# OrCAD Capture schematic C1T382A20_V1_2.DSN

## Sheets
1 002_POWER TREE: title: TELINK; rev: V1.2; note: C1T382A20
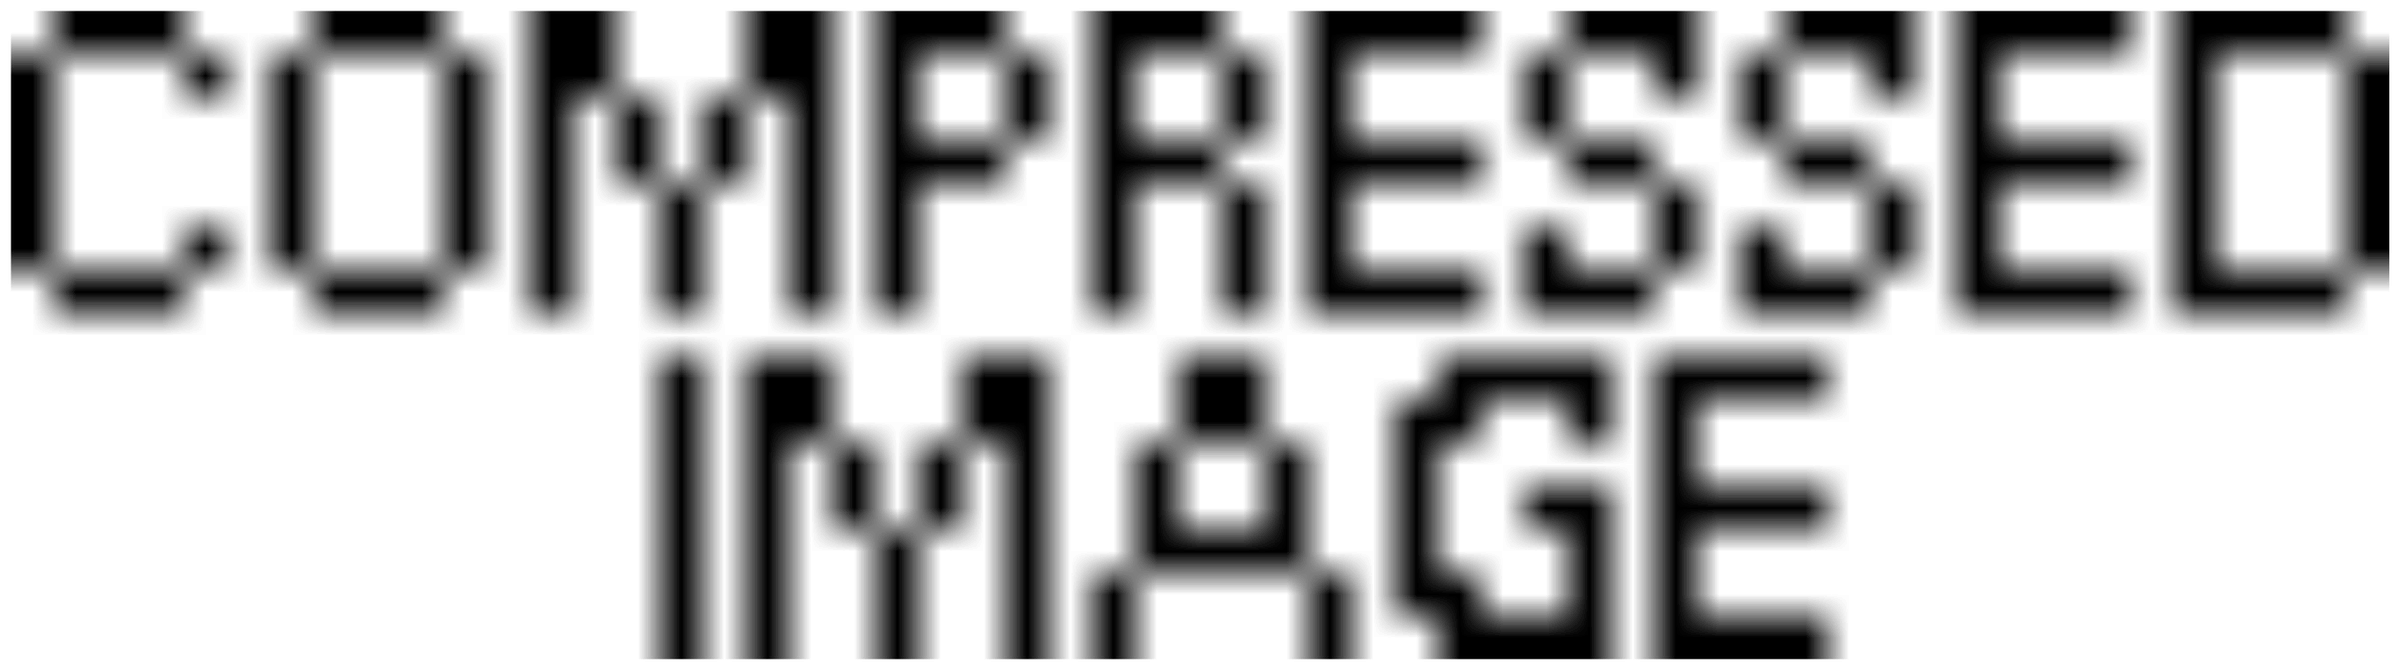
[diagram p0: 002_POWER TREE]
2 000_Log
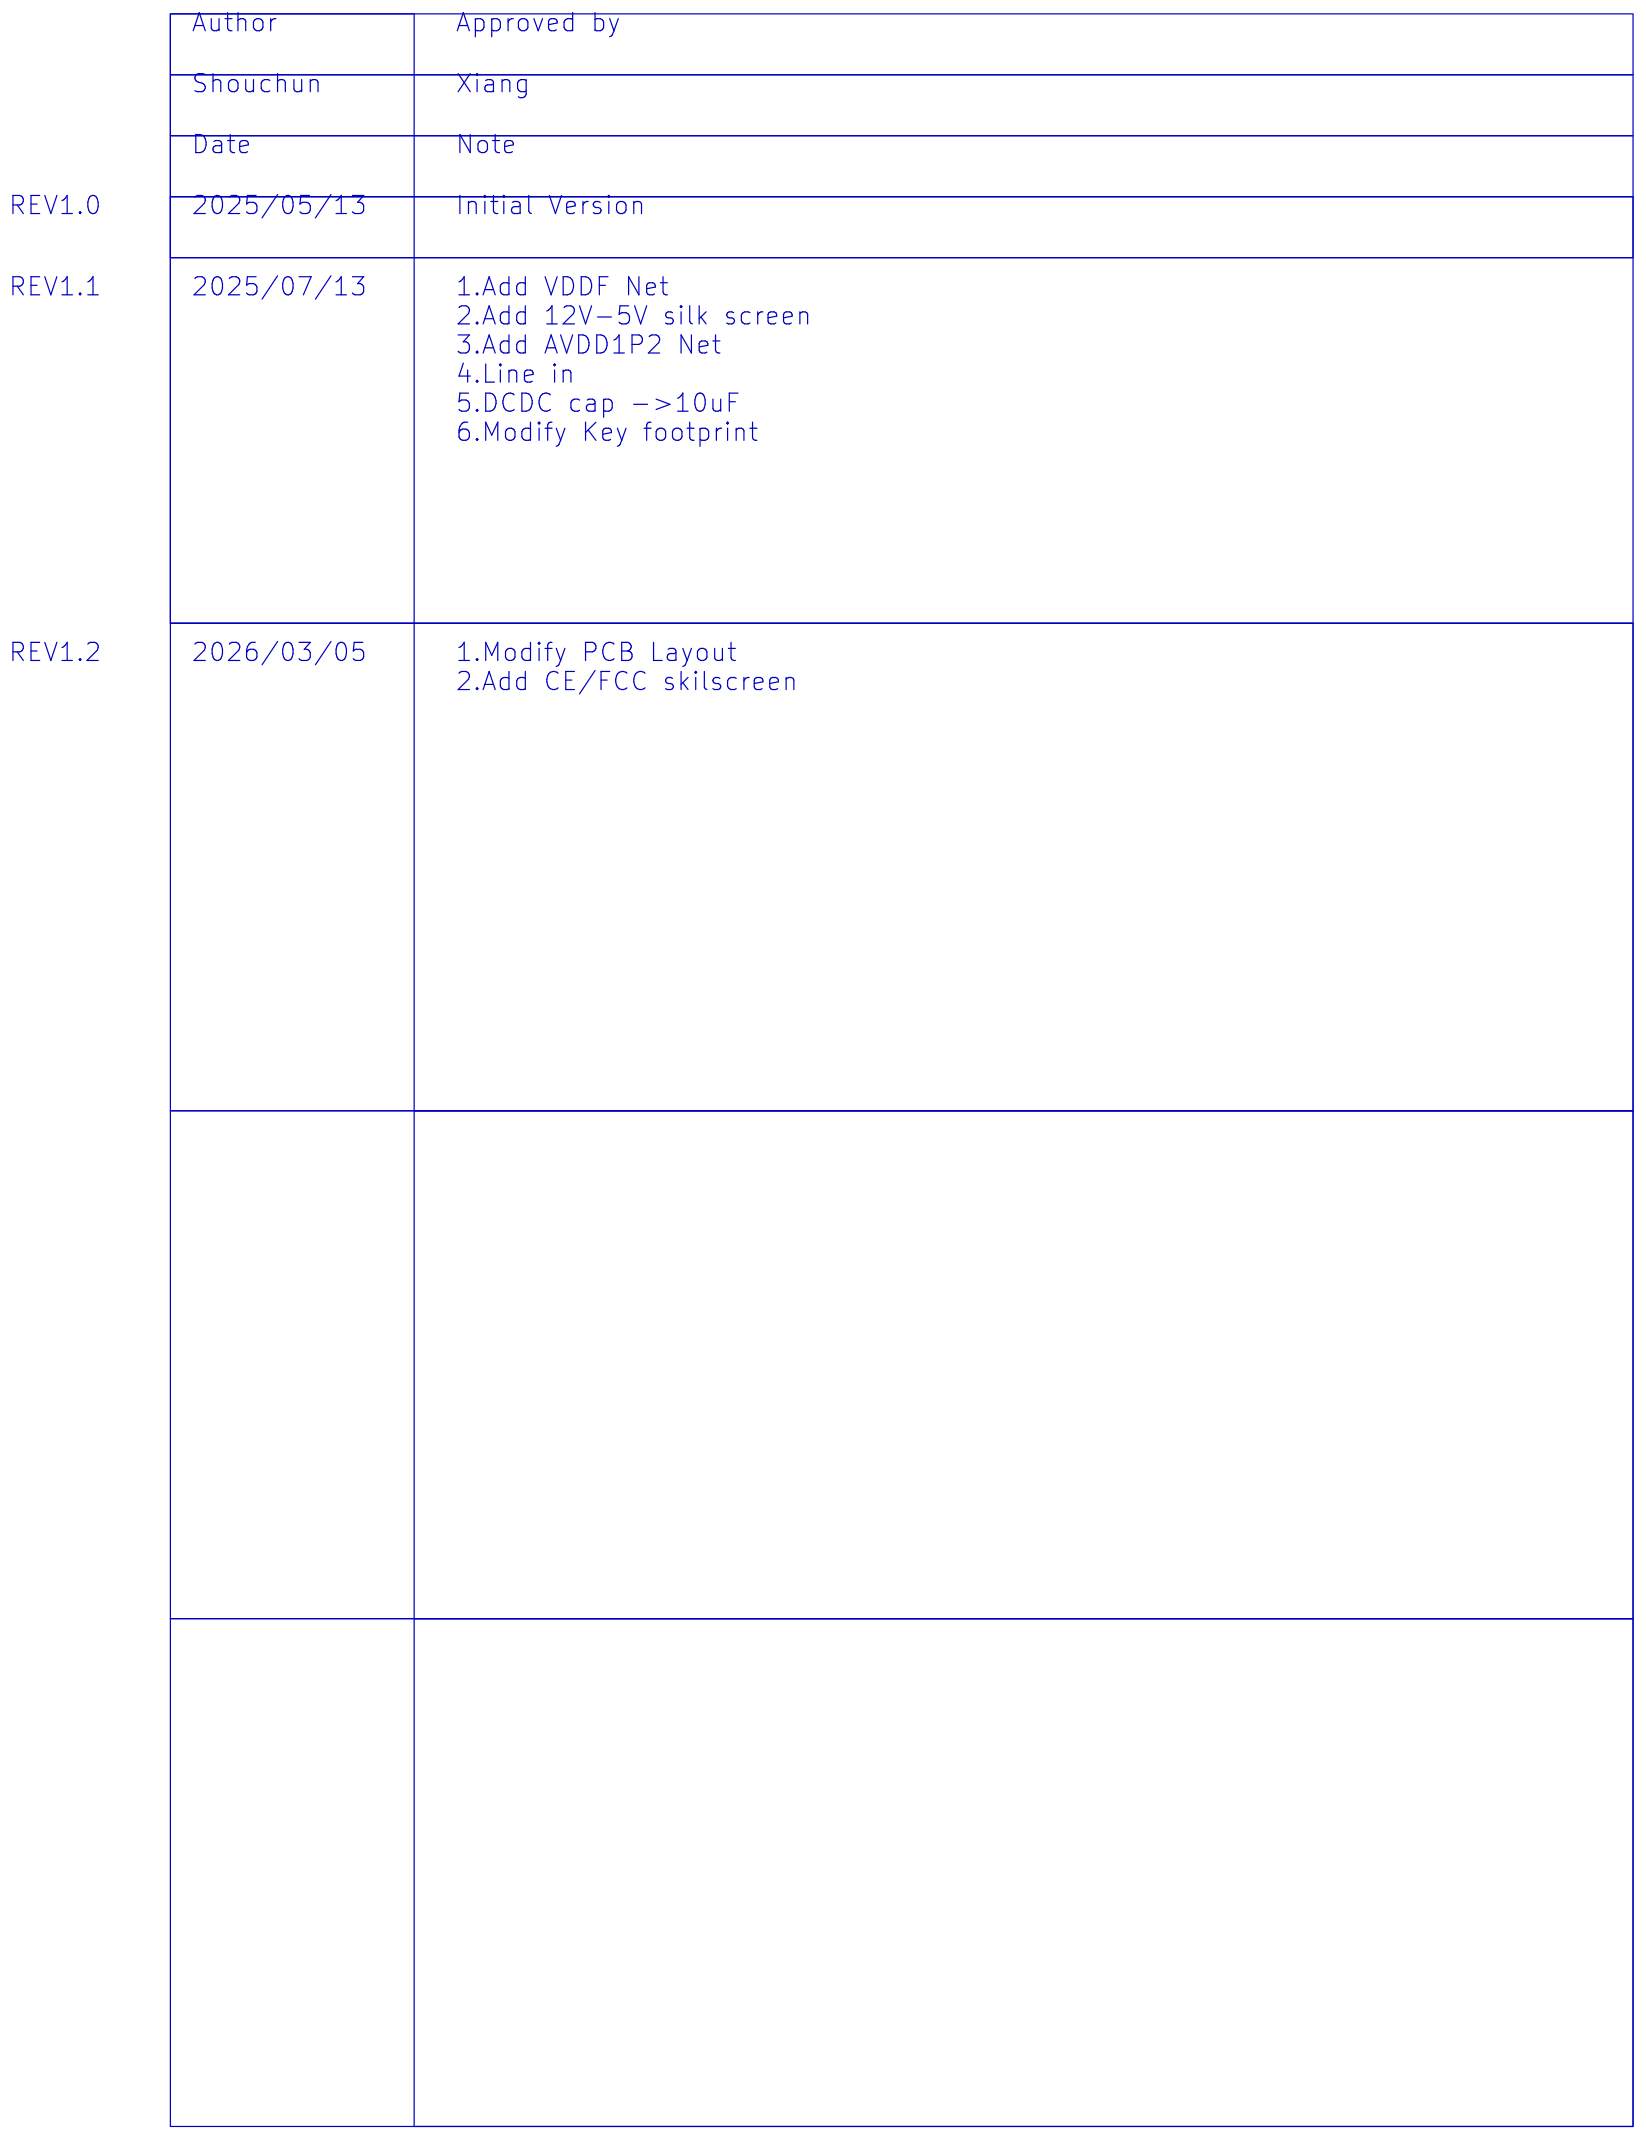
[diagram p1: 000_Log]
3 001_Sturcture
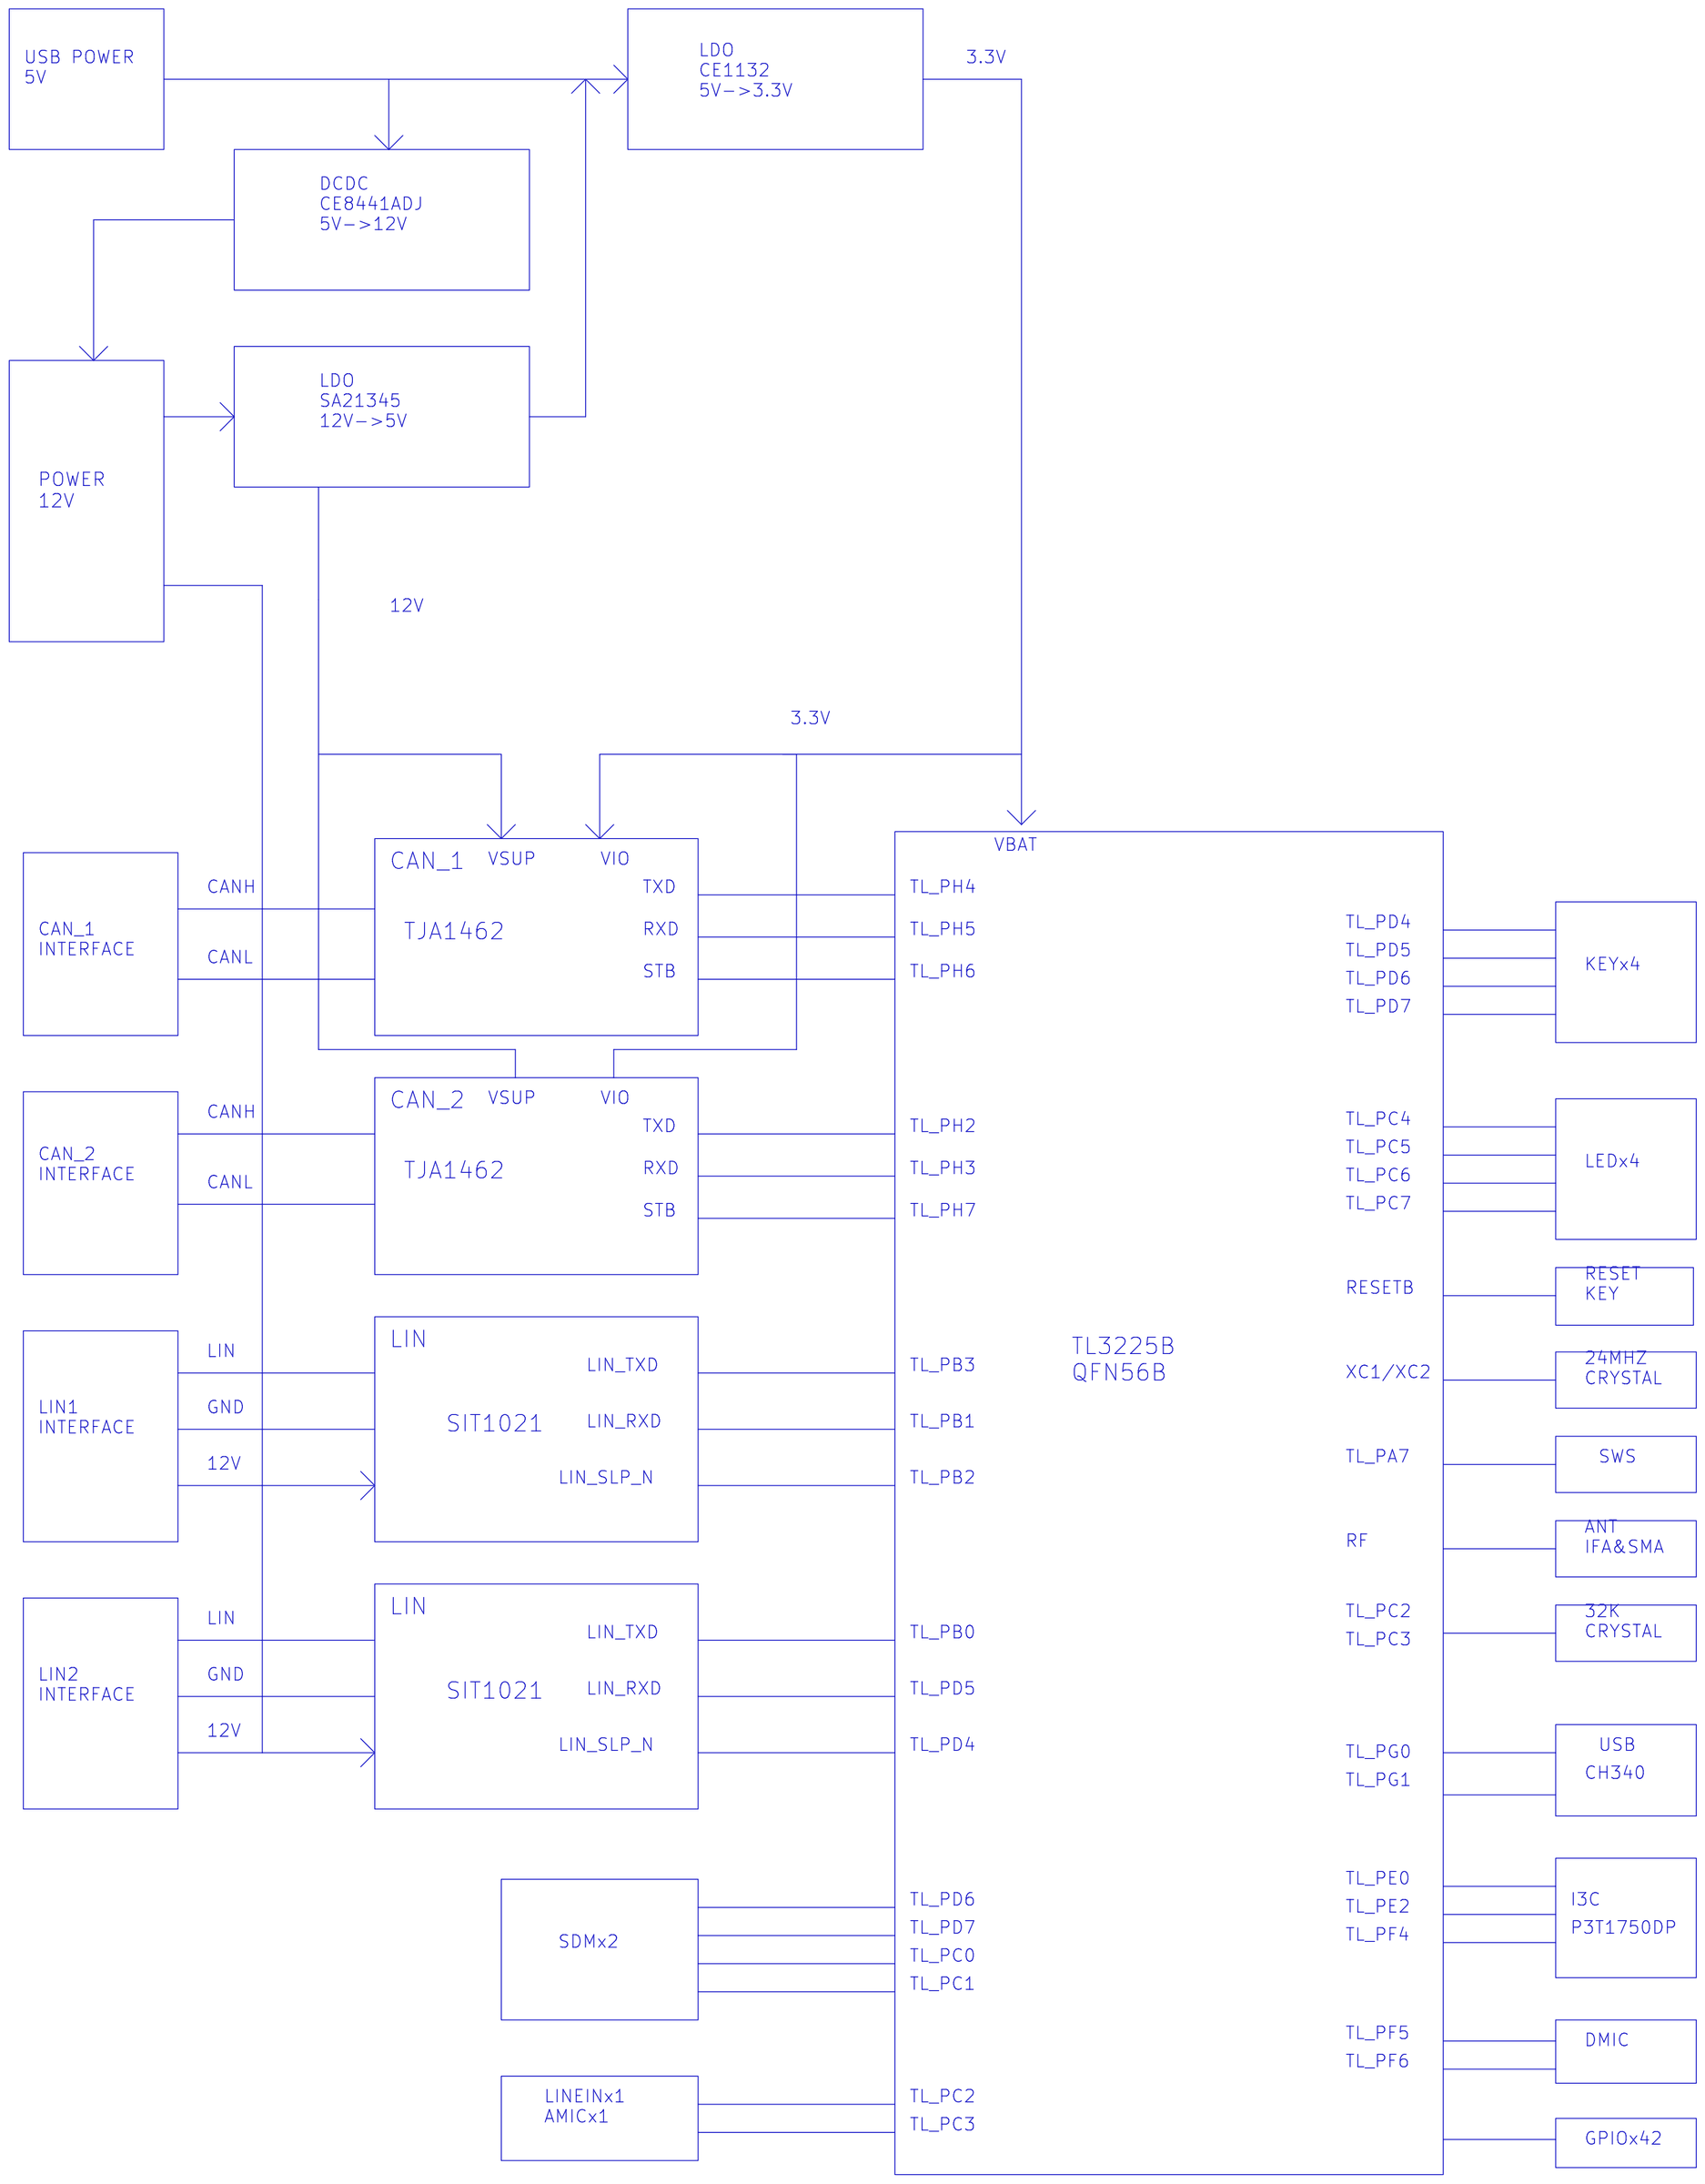
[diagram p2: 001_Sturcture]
4 003_MAIN: size A3
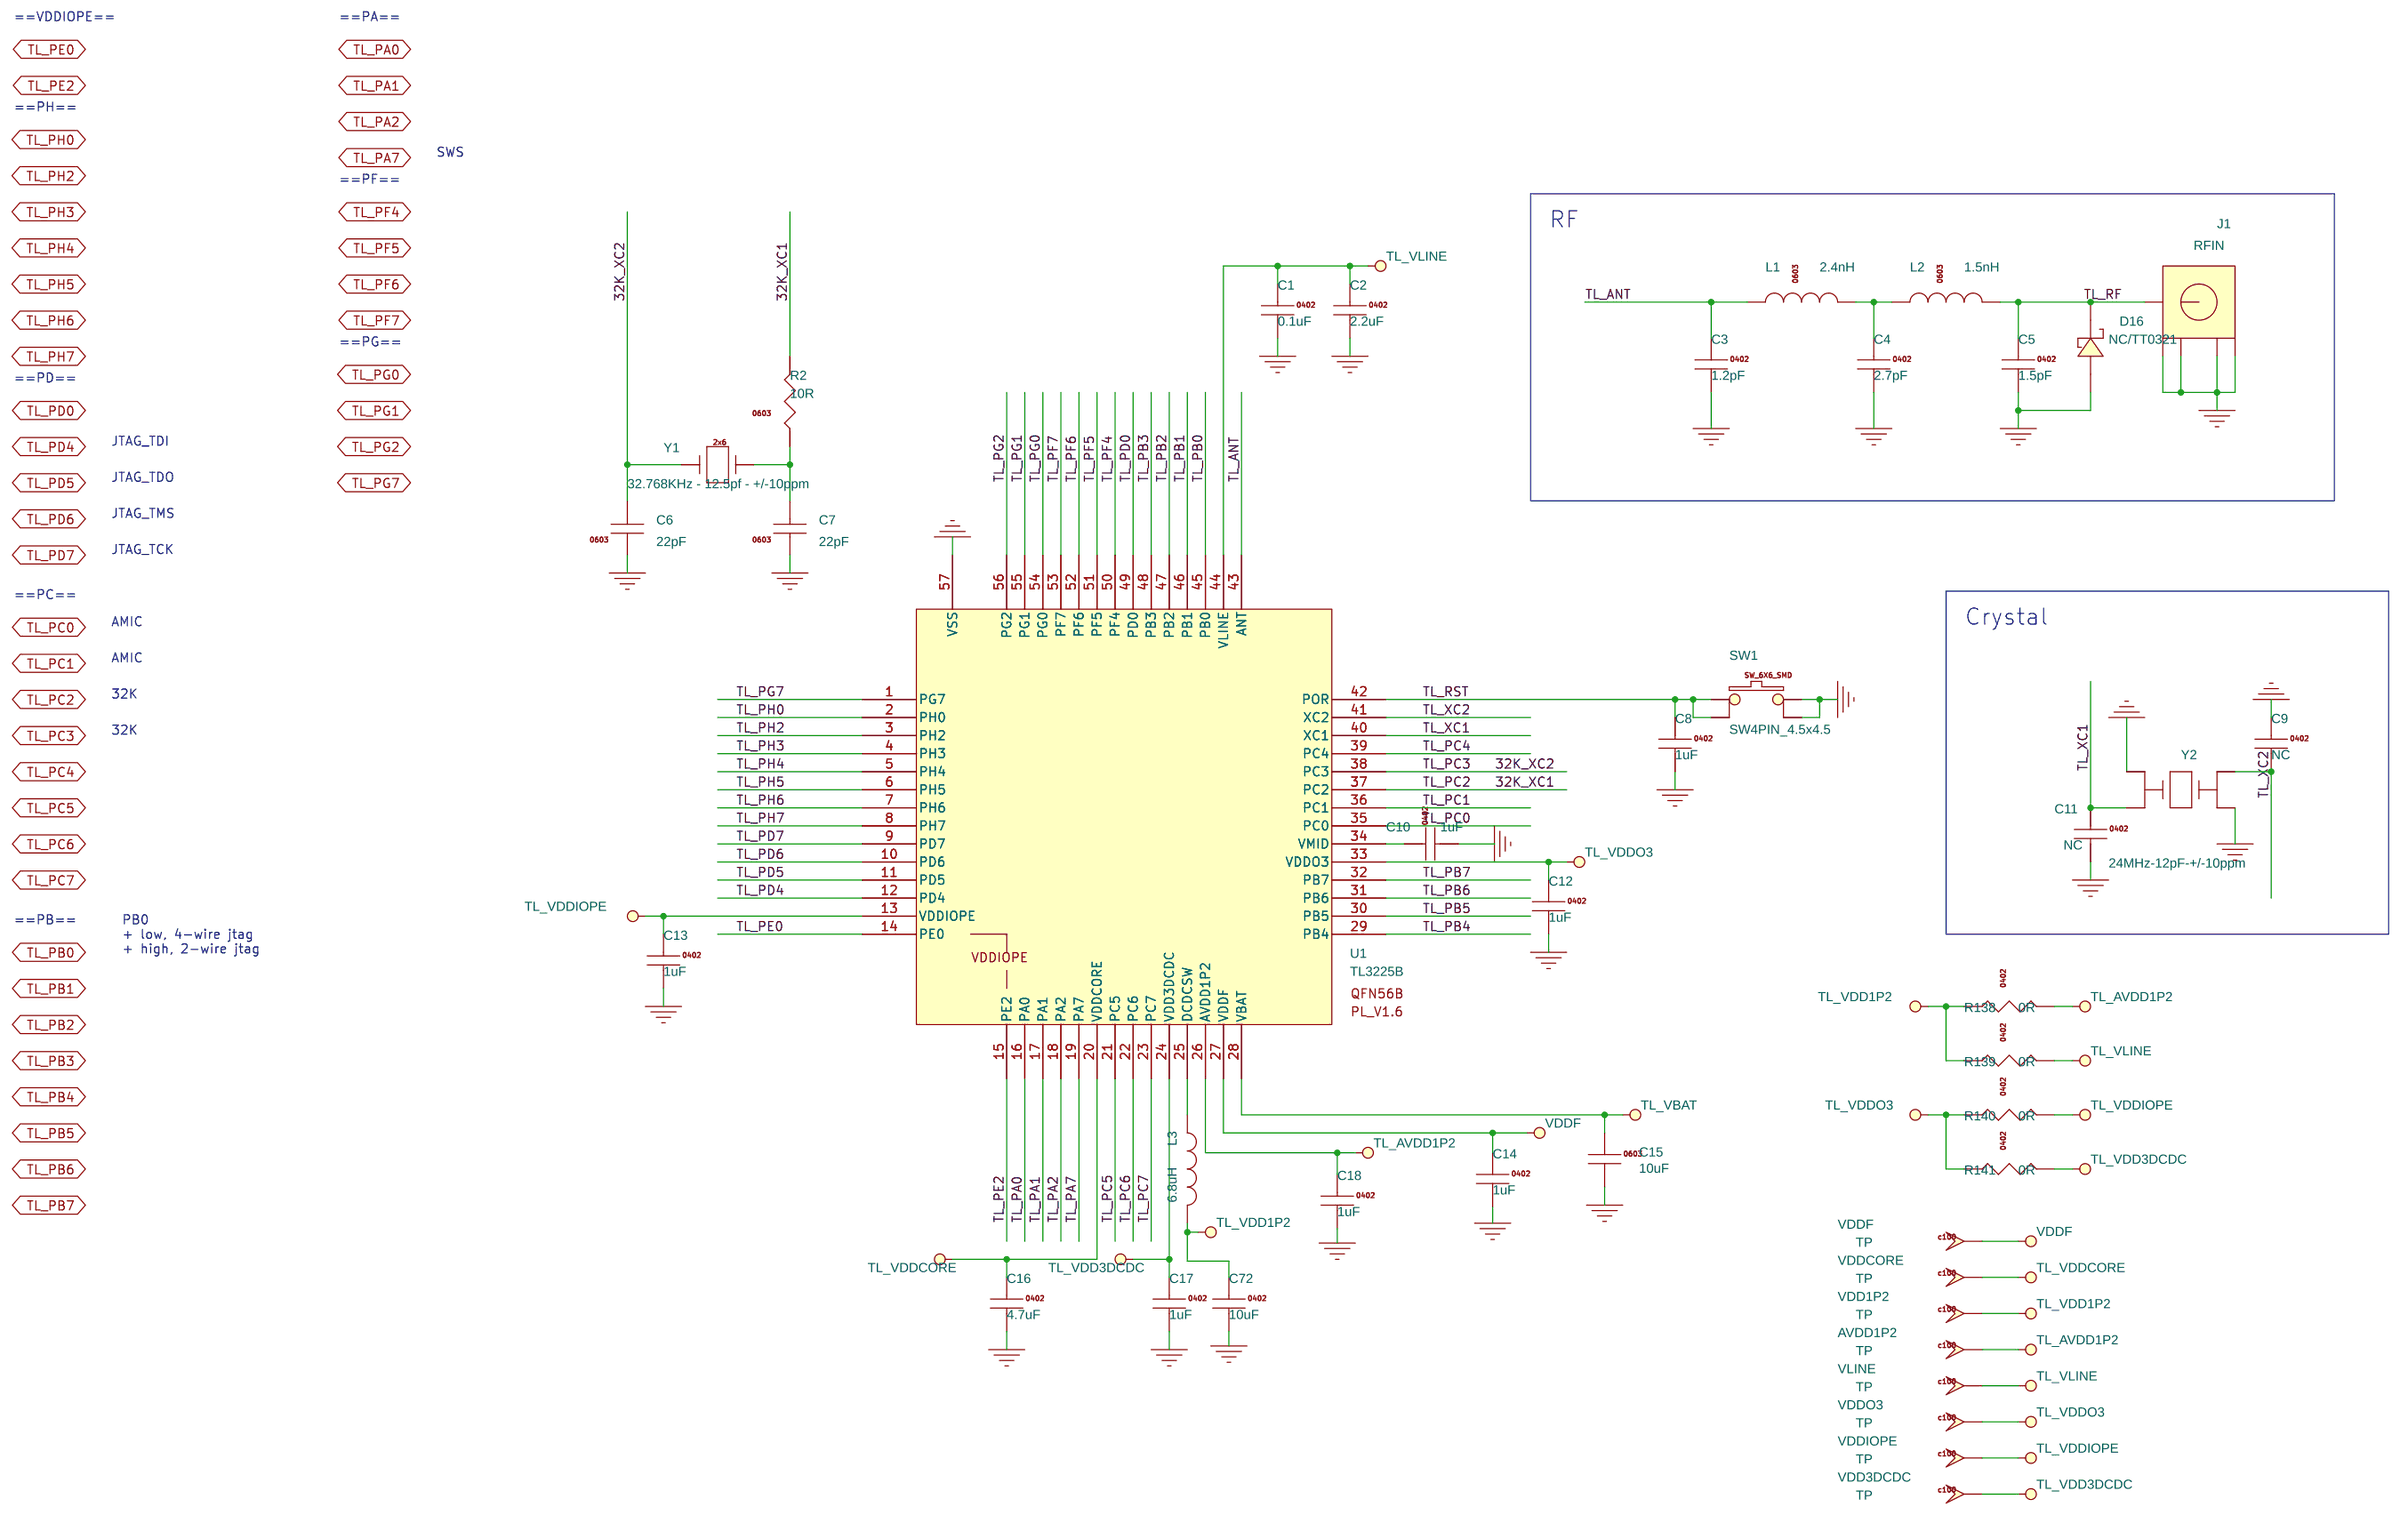
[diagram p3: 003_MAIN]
5 004_AUDIO: size A4
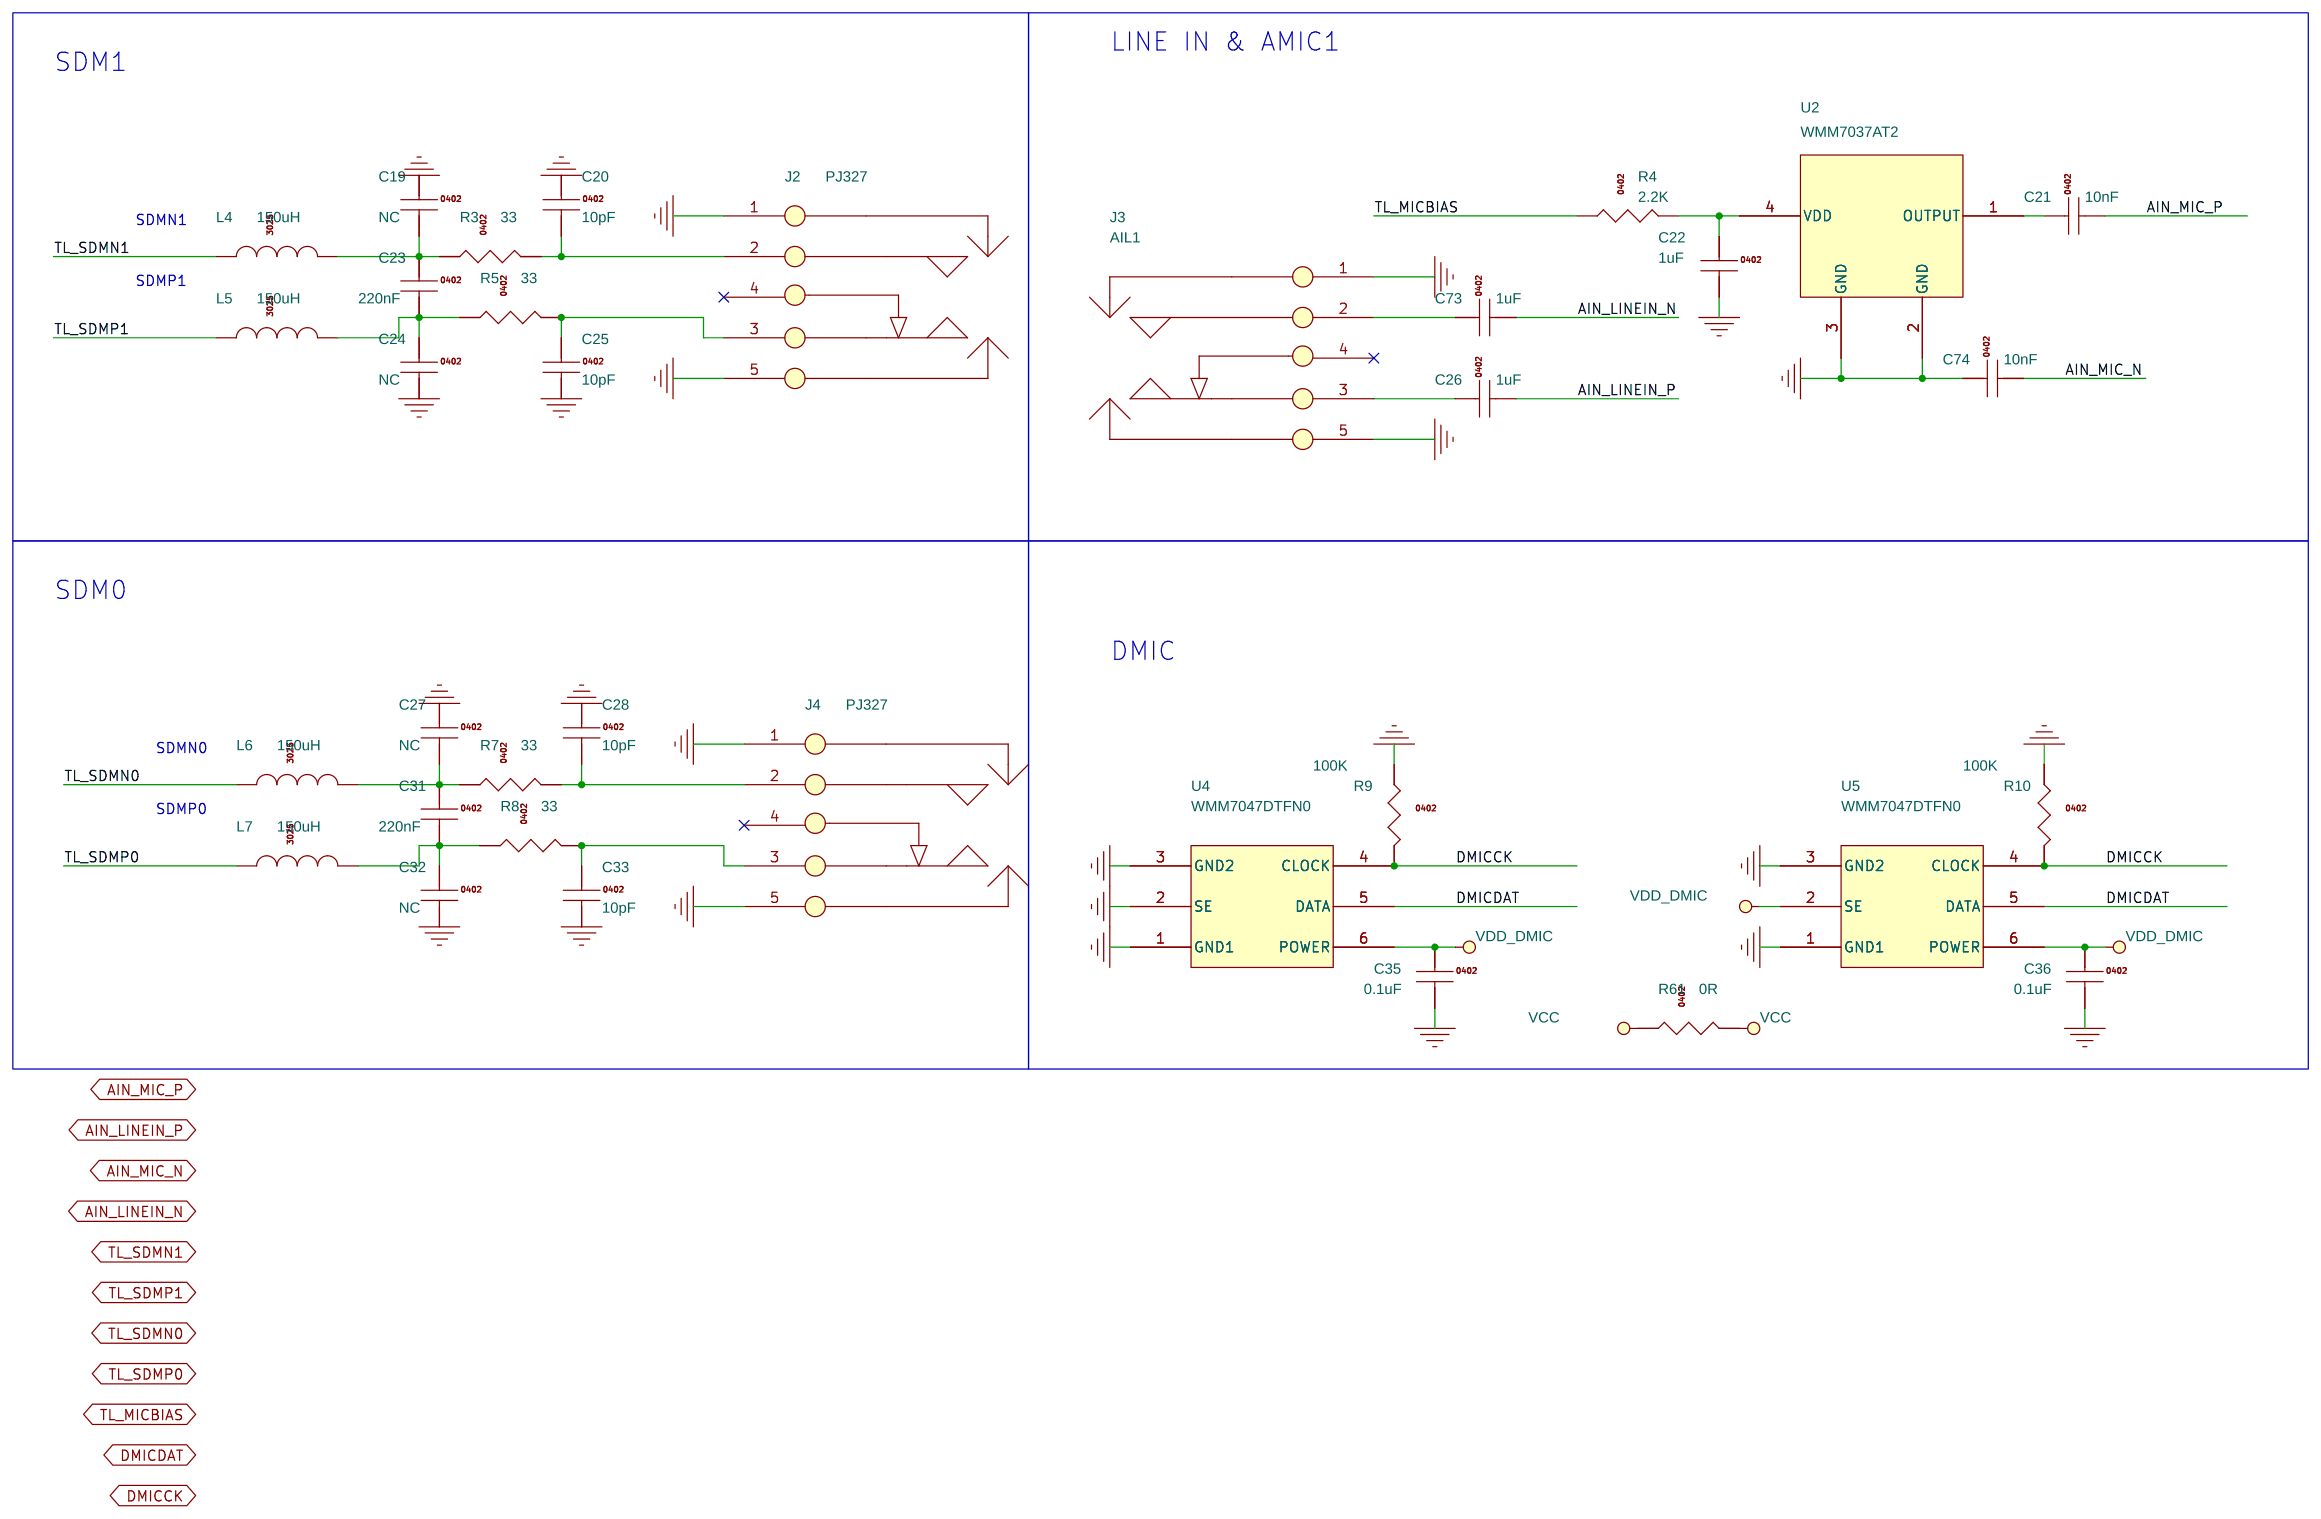
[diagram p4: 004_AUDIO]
6 005_INTERFACE: size A3
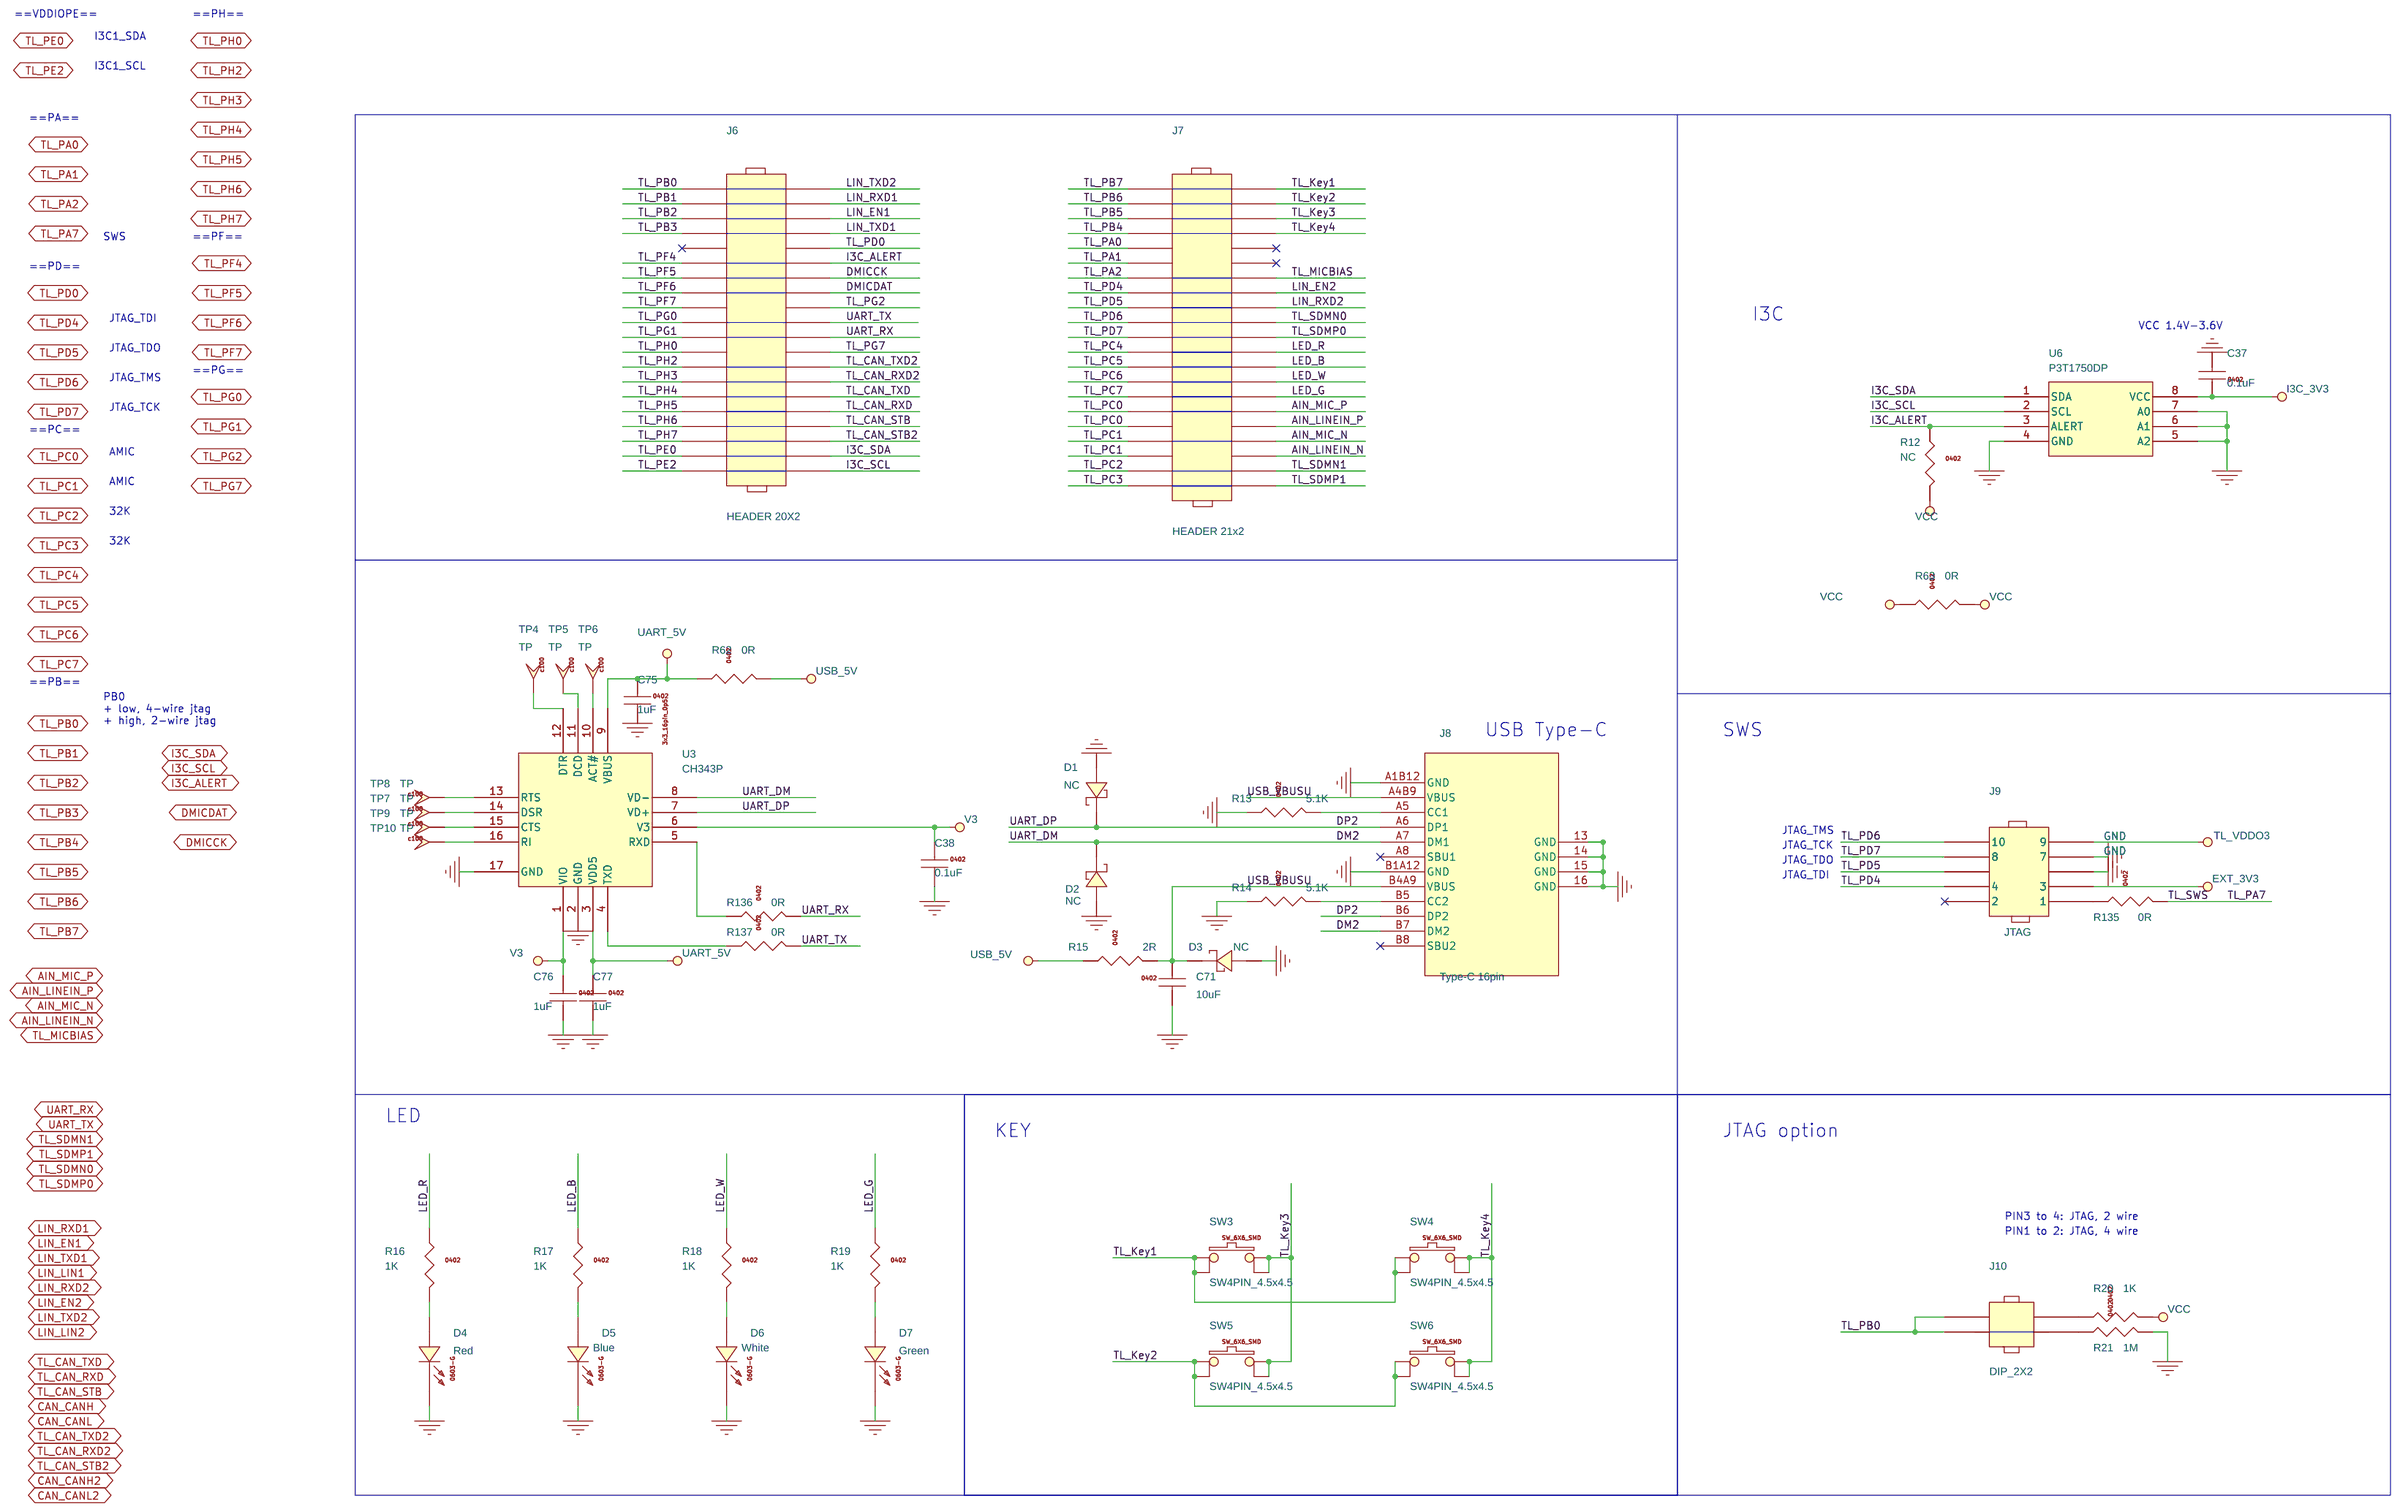
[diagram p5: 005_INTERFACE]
7 006_CAN&LIN: size A3
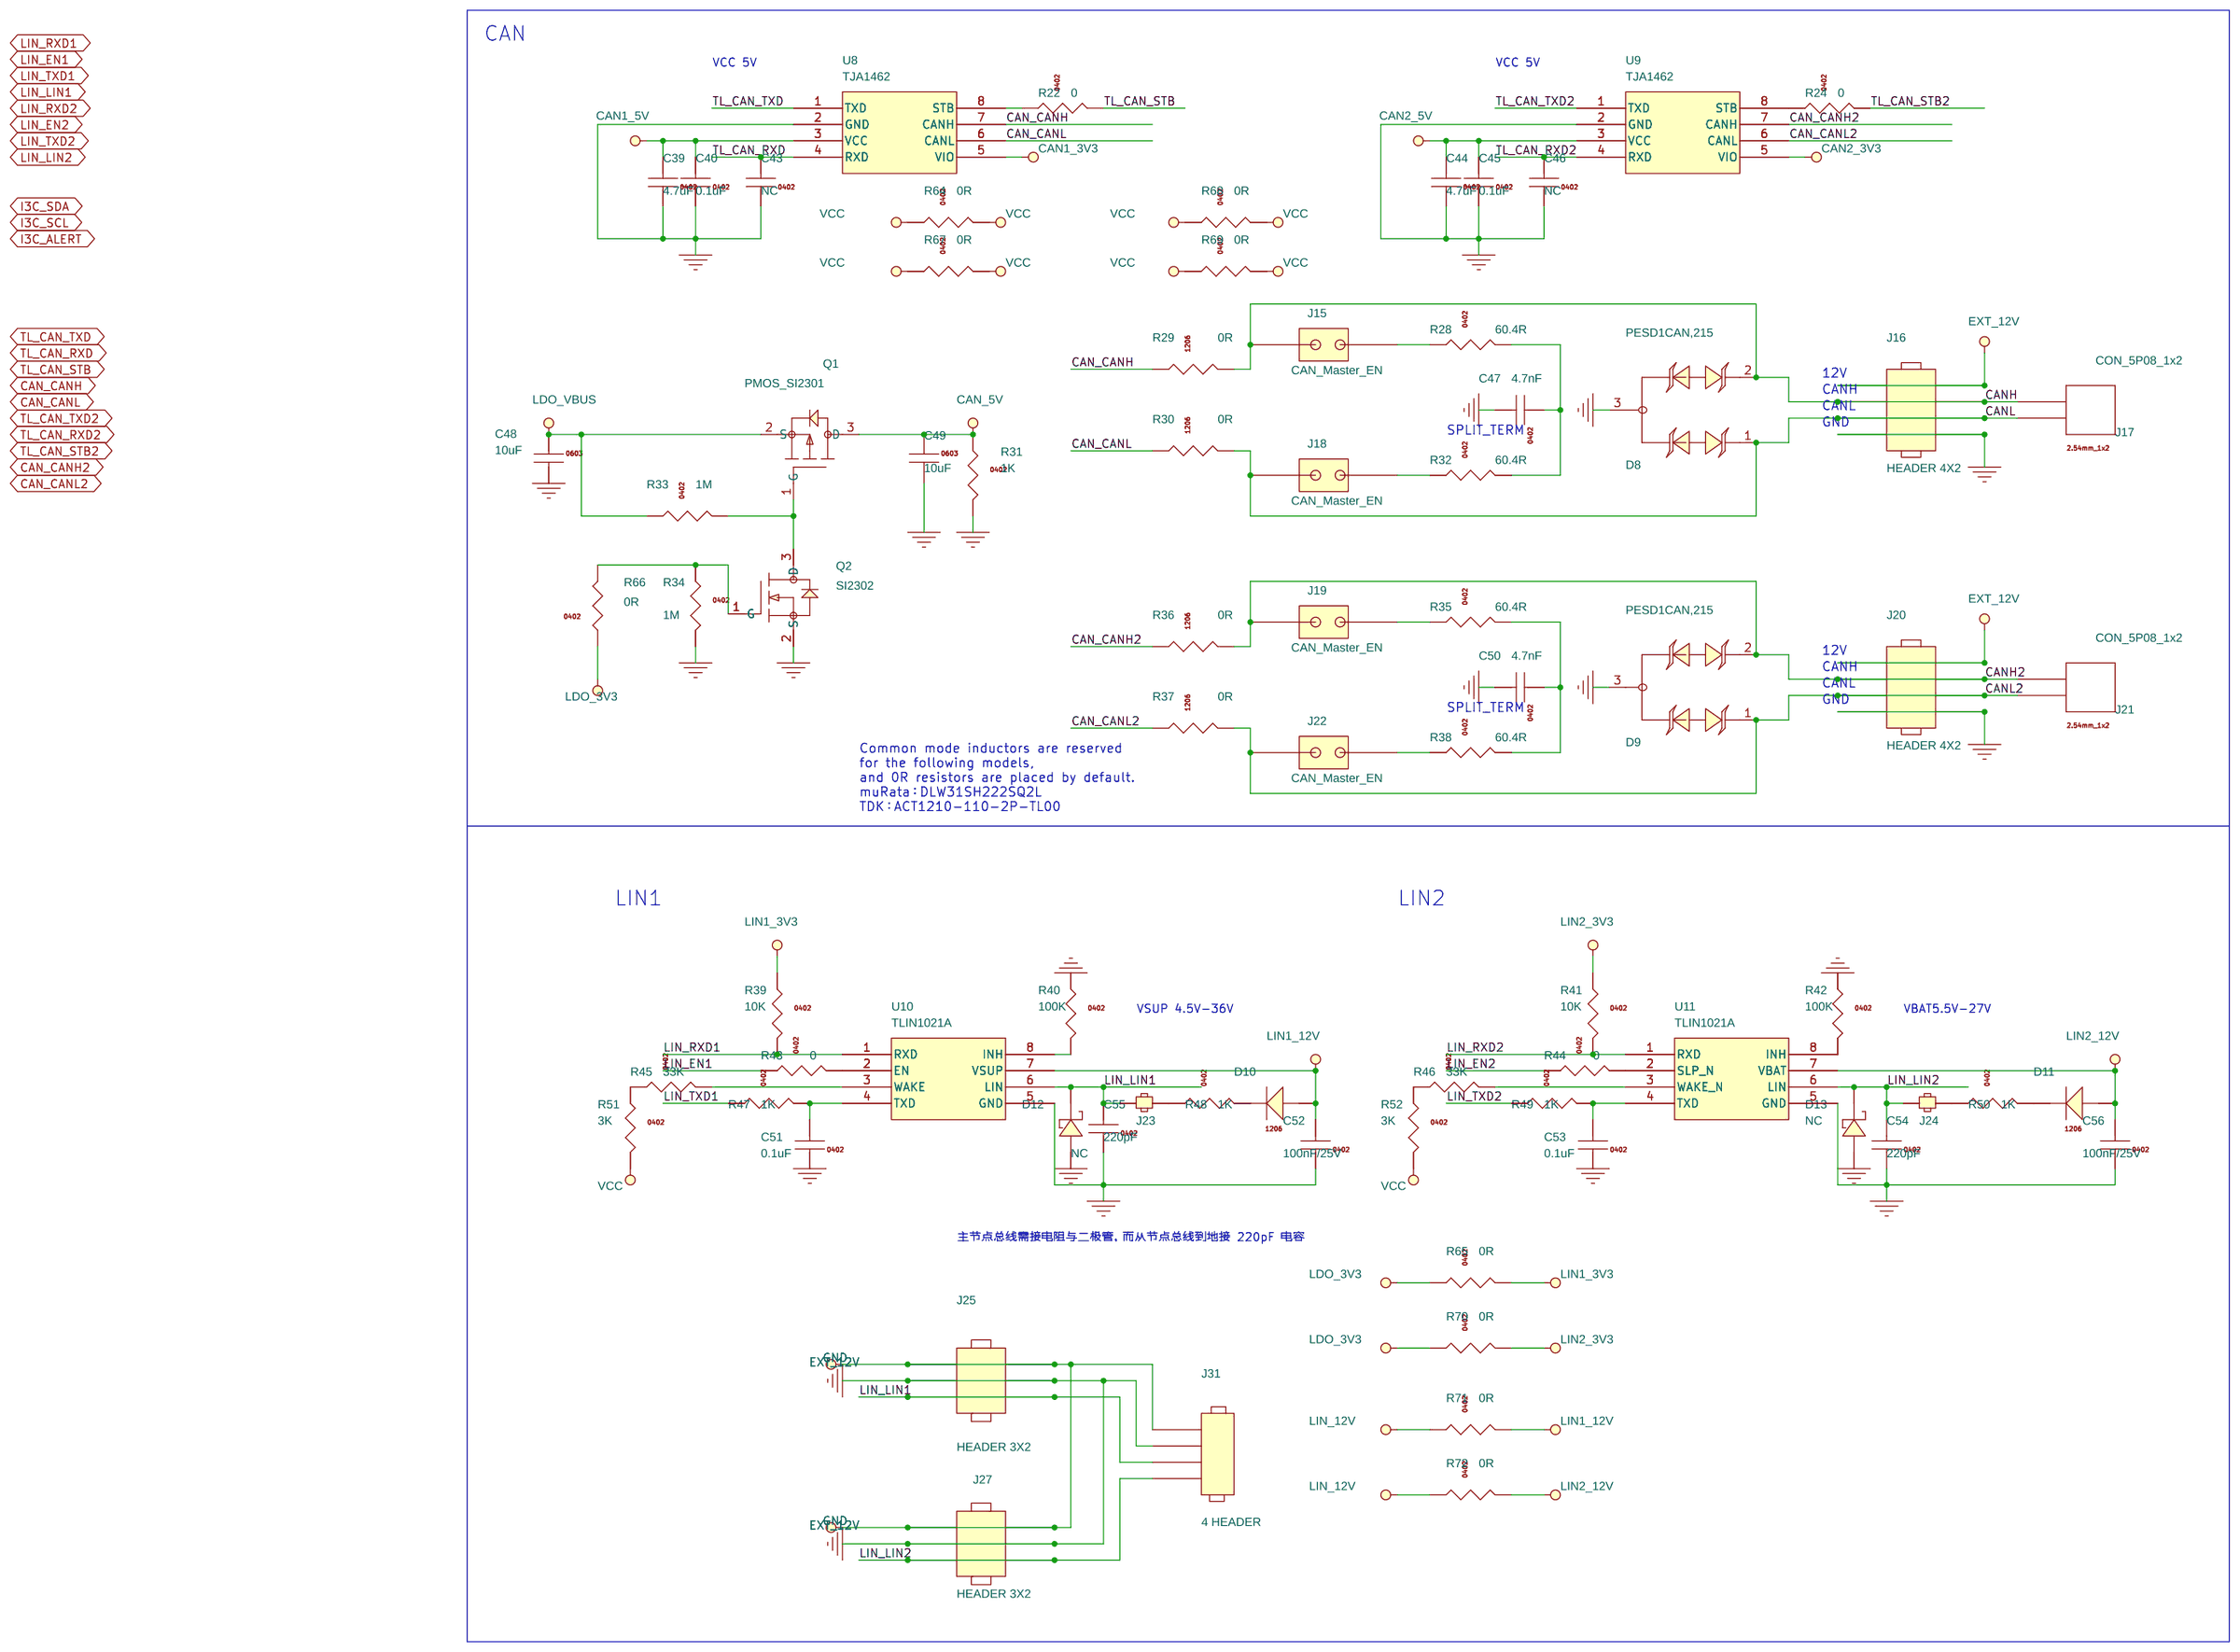
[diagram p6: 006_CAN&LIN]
8 007_PWR: size A3
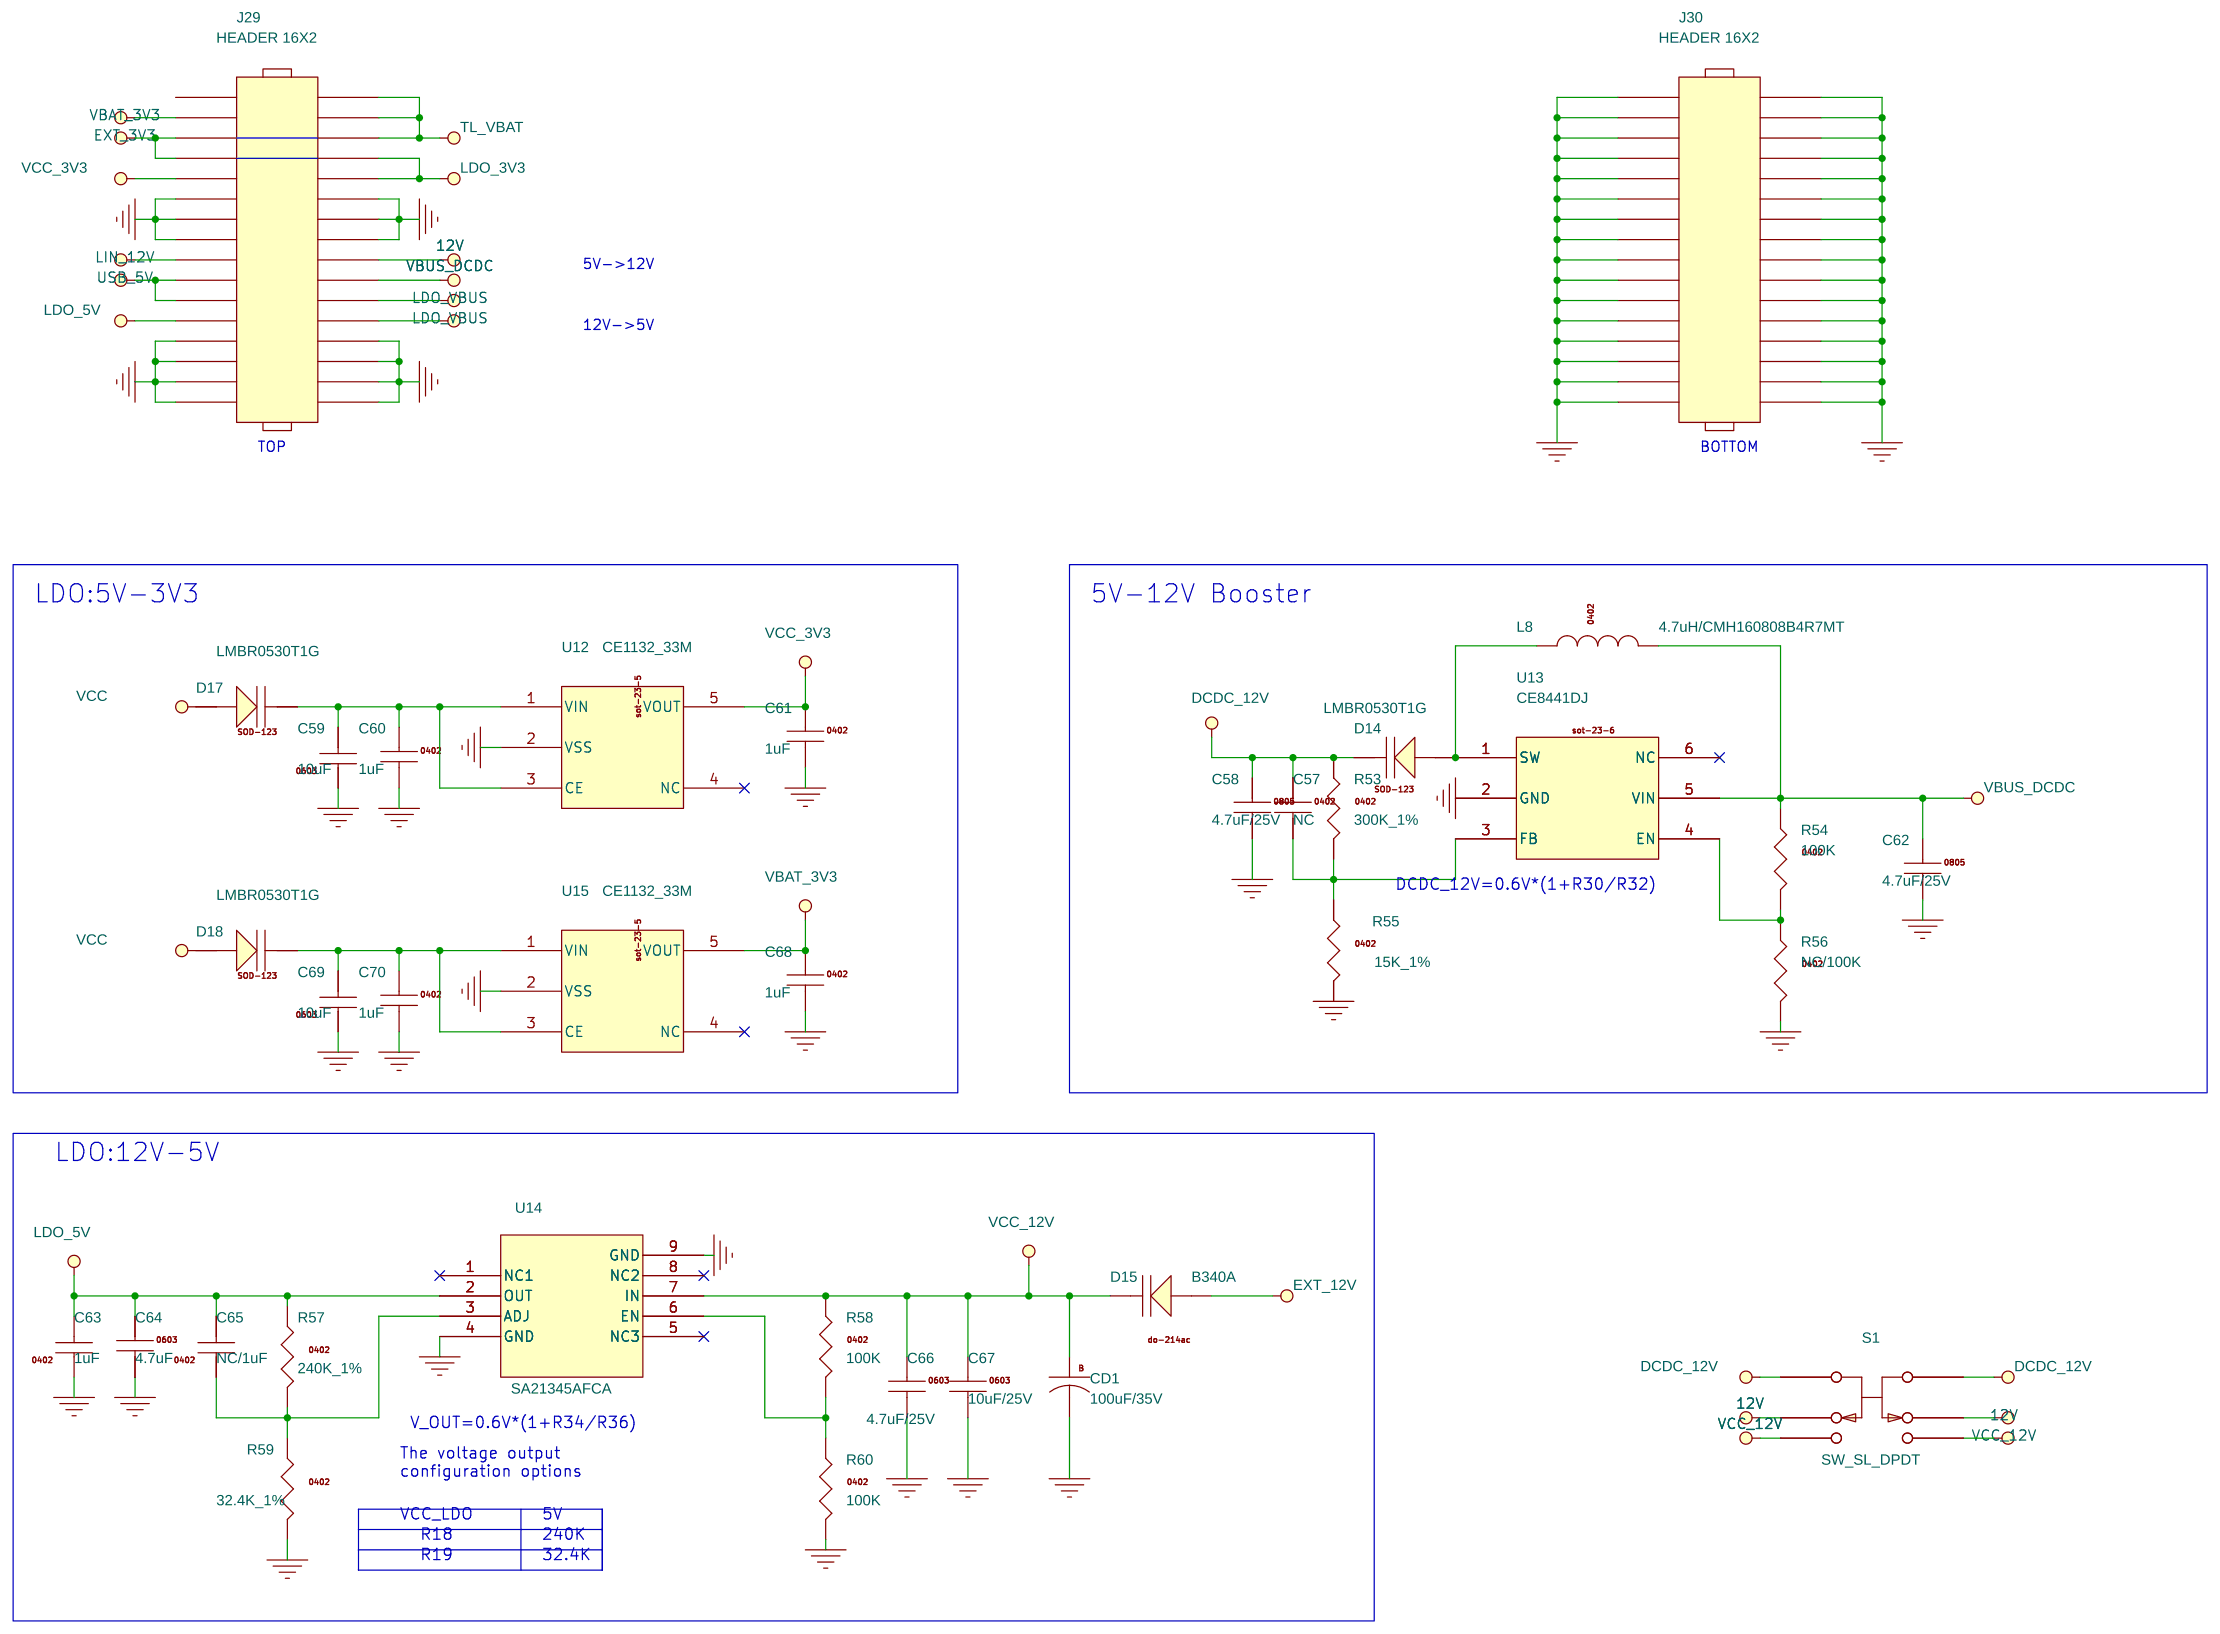
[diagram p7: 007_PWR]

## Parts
sheet 003_MAIN
AVDD1P2  TP  [TP100]
C1  0.1uF  [0402]
C2  2.2uF  [0402]
C3  1.2pF  [0402]
C4  2.7pF  [0402]
C5  1.5pF  [0402]
C6  22pF  [0402]
C7  22pF  [0402]
C8  1uF  [0402]
C9  NC  [0402]
C10  1uF  [0402]
C11  NC  [0402]
C12  1uF  [0402]
C13  1uF  [0402]
C14  1uF  [0402]
C15  10uF  [0603C]
C16  4.7uF  [0402]
C17  1uF  [0402]
C18  1uF  [0402]
C72  10uF  [0402]
D16  NC/TT0321  [0402]
J1  RFIN  [SMA-H]
L1  2.4nH  [0402]
L2  1.5nH  [0402]
L3  6.8uH  [1008L]
R2  10R  [0402]
R138  0R  [0402]
R139  0R  [0402]
R140  0R  [0402]
R141  0R  [0402]
SW1  SW4PIN_4.5x4.5  [SW_6X6_SMD]
U1  TL3225B  [qfn_7x7_56pin_0p4_5p60x5p60]
VDD1P2  TP  [TP100]
VDD3DCDC  TP  [TP100]
VDDCORE  TP  [TP100]
VDDF  TP  [TP100]
VDDIOPE  TP  [TP100]
VDDO3  TP  [TP100]
VLINE  TP  [TP100]
Y1  32.768KHz - 12.5pf - +/-10ppm  [OSC-ABS07]
Y2  24MHz-12pF-+/-10ppm  [OSCCC250X320X110]
sheet 004_AUDIO
C19  NC  [0402]
C20  10pF  [0402]
C21  10nF  [0402]
C22  1uF  [0402]
C23  220nF  [0402]
C24  NC  [0402]
C25  10pF  [0402]
C26  1uF  [0402]
C27  NC  [0402]
C28  10pF  [0402]
C31  220nF  [0402]
C32  NC  [0402]
C33  10pF  [0402]
C35  0.1uF  [0402]
C36  0.1uF  [0402]
C73  1uF  [0402]
C74  10nF  [0402]
J2  PJ327  [PJ-327]
J3  AIL1  [PJ-327]
J4  PJ327  [PJ-327]
L4  150uH  [INDM3025X25]
L5  150uH  [INDM3025X25]
L6  150uH  [INDM3025X25]
L7  150uH  [INDM3025X25]
R3  33  [0402R]
R4  2.2K  [0402]
R5  33  [0402R]
R7  33  [0402R]
R8  33  [0402R]
R9  100K  [0402]
R10  100K  [0402]
R61  0R  [0402R]
U2  WMM7037AT2  [ga_bfa423_a83]
U4  WMM7047DTFN0  [DMIC_SPM0423HM4H-WB]
U5  WMM7047DTFN0  [DMIC_SPM0423HM4H-WB]
sheet 005_INTERFACE
C37  0.1uF  [0402]
C38  0.1uF  [0402]
C71  10uF  [0402]
C75  1uF  [0402]
C76  1uF  [0402]
C77  1uF  [0402]
D1  NC  [0201]
D2  NC  [0201]
D3  NC  [0402]
D4  Red  [0603-LED]
D5  Blue  [0603-LED]
D6  White  [0603-LED]
D7  Green  [0603-LED]
J6  HEADER 20X2  [HDR2X20-2R54-SM-VM]
J7  HEADER 21x2  [HDR2X21-2R54-SM-M]
J8  Type-C 16pin  [type_c_cq_105pwb]
J9  JTAG  [HDR254F-2X5X850]
J10  DIP_2X2  [DipSwitch_2p54_7p62_2x2]
R12  NC  [0402]
R13  5.1K  [0402]
R14  5.1K  [0402]
R15  2R  [0603r]
R16  1K  [0402]
R17  1K  [0402]
R18  1K  [0402]
R19  1K  [0402]
R20  1K  [0402]
R21  1M  [0402]
R62  0R  [0402R]
R63  0R  [0402R]
R135  0R  [0402]
R136  0R  [0402]
R137  0R  [0402]
SW3  SW4PIN_4.5x4.5  [SW_6X6_SMD]
SW4  SW4PIN_4.5x4.5  [SW_6X6_SMD]
SW5  SW4PIN_4.5x4.5  [SW_6X6_SMD]
SW6  SW4PIN_4.5x4.5  [SW_6X6_SMD]
TP4  TP  [TP100]
TP5  TP  [TP100]
TP6  TP  [TP100]
TP7  TP  [TP100]
TP8  TP  [TP100]
TP9  TP  [TP100]
TP10  TP  [TP100]
U3  CH343P  [qfn_3x3_16pin_0p5_1p70x1p70]
U6  P3T1750DP  [SOT505-1]
sheet 006_CAN&LIN
C39  4.7uF  [0402]
C40  0.1uF  [0402]
C43  NC  [0402]
C44  4.7uF  [0402]
C45  0.1uF  [0402]
C46  NC  [0402]
C47  4.7nF  [0402]
C48  10uF  [0402]
C49  10uF  [0402]
C50  4.7nF  [0402]
C51  0.1uF  [0402]
C52  100nF/25V  [0402]
C53  0.1uF  [0402]
C54  220pF  [0402]
C55  220pF  [0402]
C56  100nF/25V  [0402]
D8  PESD1CAN,215  [SOT-23]
D9  PESD1CAN,215  [SOT-23]
D10  4148  [SOD80]
D11  4148  [SOD80]
D12  NC  [0402]
D13  NC  [0402]
J15  CAN_Master_EN  [HDR254F-1X2X850]
J16  HEADER 4X2  [hdr254f-2x4x850]
J17  CON_5P08_1x2  [con_5p08_1x2]
J18  CAN_Master_EN  [HDR254F-1X2X850]
J19  CAN_Master_EN  [HDR254F-1X2X850]
J20  HEADER 4X2  [hdr254f-2x4x850]
J21  CON_5P08_1x2  [con_5p08_1x2]
J22  CAN_Master_EN  [HDR254F-1X2X850]
J23  can1  [hdr254f-1x2x850]
J24  can1  [hdr254f-1x2x850]
J25  HEADER 3X2  [hdr254f-2x3x850]
J27  HEADER 3X2  [hdr254f-2x3x850]
J31  4 HEADER  [CON_5P08_1X4]
Q1  PMOS_SI2301  [mos_sot-23]
Q2  SI2302  [mos_sot-23]
R22  0  [0402]
R24  0  [0402]
R28  60.4R  [0805R]
R29  0R  [1206R]
R30  0R  [1206R]
R31  1K  [0402]
R32  60.4R  [0805R]
R33  1M  [0402]
R34  1M  [0402]
R35  60.4R  [0805R]
R36  0R  [1206R]
R37  0R  [1206R]
R38  60.4R  [0805R]
R39  10K  [0402]
R40  100K  [0402]
R41  10K  [0402]
R42  100K  [0402]
R43  0  [0402]
R44  0  [0402]
R45  33K  [0402]
R46  33K  [0402]
R47  1K  [0402]
R48  1K  [0402]
R49  1K  [0402]
R50  1K  [0402]
R51  3K  [0402]
R52  3K  [0402]
R64  0R  [0402R]
R65  0R  [0402R]
R66  0R  [0402R]
R67  0R  [0402R]
R68  0R  [0402R]
R69  0R  [0402R]
R70  0R  [0402R]
R71  0R  [0402R]
R72  0R  [0402R]
U8  TJA1462  [sop8-1r27-7r40x5r50]
U9  TJA1462  [sop8-1r27-7r40x5r50]
U10  TLIN1021A  [sop8-1r27-7r40x5r50]
U11  TLIN1021A  [sop8-1r27-7r40x5r50]
sheet 007_PWR
C57  NC  [0402]
C58  4.7uF/25V  [0805C]
C59  10uF  [0603C]
C60  1uF  [0402]
C61  1uF  [0402]
C62  4.7uF/25V  [0805C]
C63  1uF  [0402]
C64  4.7uF  [0603C]
C65  NC/1uF  [0402]
C66  4.7uF/25V  [0603C]
C67  10uF/25V  [0603C]
C68  1uF  [0402]
C69  10uF  [0603C]
C70  1uF  [0402]
CD1  100uF/35V  [VZH101M1VTR-0607]
D14  LMBR0530T1G  [sod-123]
D15  B340A  [do-214ac]
D17  LMBR0530T1G  [sod-123]
D18  LMBR0530T1G  [sod-123]
J29  HEADER 16X2  [HDR2X16-2R54-SM-M]
J30  HEADER 16X2  [HDR2X16-2R54-SM-M]
L8  4.7uH/CMH160808B4R7MT  [0603l]
R53  300K_1%  [0402]
R54  100K  [0402]
R55  15K_1%  [0402]
R56  NC/100K  [0402]
R57  240K_1%  [0402]
R58  100K  [0402]
R59  32.4K_1%  [0402]
R60  100K  [0402]
S1  SW_SL_DPDT  [sw-th-6pin-3_60x9_00-34np]
U12  CE1132_33M  [sot-23-5]
U13  CE8441DJ  [sot-23-6l_0p95]
U14  SA21345AFCA  [w25x10_20_40bl_GND]
U15  CE1132_33M  [sot-23-5]

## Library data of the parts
AVDD1P2 TP4-TP10 VDD1P2 VDD3DCDC VDDCORE VDDF VDDIOPE VDDO3 VLINE = TestPad100
C1-C5 C8-C14 C16-C19 C24 C27 C32 C38 C72 C75-C77 = C1005_NC
C6 C7 C59 C69 = C1608_NC
C15 C48 C49 C64 C66 C67 = C1608X5R0J106M
D1-D3 D12 D13 D16 = DIODE_SCHOTTKY_0
J1 = SMA_JACK_2: PART: RF
L1 L2 = MLK1608_000R
L3 = IND_0
R2 = RS0603K102JT
R33 R34 R138-R141 = RS0402K105JT
SW1 SW3-SW6 = SW_6X6_SMD_0
U1 = TL3225B_QFN56
Y1 = OSC_2x6_2pin_16Mhz
Y2 = CRYSTAL4_SM_0
C20 C25 C28 C33 = C1005C0G1H100D
C21 C22 C26 C37 C39 C40 C43-C47 C50-C56 C63 C65 C71 C73 C74 = C1005X5R1C104K
C23 C31 = C1005X5R1C224M
C35 C36 = C1005X5R1C104K_1
J2-J4 = PJ327_2
L4-L7 = IND_150uH_3025
R3 R5 R7 R8 R61-R72 = RS0402K330JT
R4 R9 R10 R12 R20-R22 R24 R39-R52 R54 R56 R58 R60 R135 = RS0402K104JT
U2 = MULPS4CX-RM5_0
U4 = LD1117_SO_0
U5 = LD1117_SO_1
D4-D7 = 0603D_Green
J6 = HEADER_20X2
J7 = HEADER_21x2
J8 = Type-C_16pin_0
J9 = CONN_PLUG_5x2
J10 = HEADER_2X2_0
R13-R15 = RS0402K330JT: ROOM: USB
R16-R19 = RS0402K101JT
R28 R31 R32 R35 R38 R136 R137 = RS0402K102JT
U3 = CH343P
U6 = P3T1750DP
D8 D9 = SM712_0
D10 = Diode_0
D11 = NC
J15 J18 J19 J22 = B2S_0
J16 J20 = HEADER_4X2
J17 J21 = CON_2.54mm_1x2
J23 J24 = HEADER_1x2_8
J25 J27 = HEADER_3X2
J31 = 4_HEADER
Q1 = PMOS_SI2301
Q2 = NMOS_SI2302
R29 R30 R36 R37 = RS1206_NC
U8 U9 = TJA1462
U10 = TLIN1021A
U11 = CA-IF1021
C57 = C1005_NC_0
C58 C62 = C2012X5R1A475M
C60 C61 C68 C70 = C1608X5R0J106M_0
CD1 = TAJC476M016RNJ
D14 D17 D18 = Diode_CDBW0520L-G
D15 = Diode_B340A
J29 J30 = HEADER_16X2
L8 = MLK1005_NC
R53 R55 = RS0402_NC_0
R57 R59 = RS0402_NC
S1 = SW_SL_DPDT
U12 U15 = CE1132_3V3_SOT-23-5
U13 = TPS61070_ADJ_SOT-23-6_0
U14 = SiT5356AI-FQ-33N0-12_2.000000

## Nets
12V: J29.17 S1.2 S1.5
GND: C1.2 C2.2 C3.2 C4.2 C5.2 C6.1 C7.1 C8.2 C9.1 C10.2 C11.2 C12.2 C13.2 C14.2 C15.2 C16.2 C17.2 C18.2 C19.1 C20.1 C22.2 C24.2 C25.2 C27.1 C28.1 C32.2 C33.2 C35.2 C36.2 C37.2 C38.2 C39.1 C40.1 C43.1 C44.1 C45.1 C46.1 C47.2 C48.2 C49.2 C50.2 C51.1 C52.1 C53.1 C54.1 C55.1 C56.1 C58.2 C59.1 C60.2 C61.2 C62.2 C63.1 C64.2 C66.2 C67.2 C68.2 C69.1 C70.2 C71.2 C72.2 C74.1 C75.2 C76.2 C77.2 CD1.2 D1.1(ANODE) D2.1(ANODE) D3.1(ANODE) D4.C(CATHODE) D5.C(CATHODE) D6.C(CATHODE) D7.C(CATHODE) D8.3 D9.3 D12.1(ANODE) D13.1(ANODE) D16.1(ANODE) J1.2 J1.3 J1.4 J1.5 J2.1 J2.5 J3.1 J3.5 J4.1 J4.5 J8.13(GND) J8.14(GND) J8.15(GND) J8.16(GND) J8.A1B12(GND) J8.B1A12(GND) J9.3(7) J9.5 J16.7 J16.8 J20.7 J20.8 J25.3 J25.4 J27.3 J27.4 J29.11 J29.12 J29.13 J29.14 J29.15 J29.16 J29.25 J29.26 J29.27 J29.28 J29.29 J29.30 J29.31 J29.32 J30.1 J30.2 J30.3 J30.4 J30.5 J30.6 J30.7 J30.8 J30.9 J30.10 J30.11 J30.12 J30.13 J30.14 J30.15 J30.16 J30.17 J30.18 J30.19 J30.20 J30.21 J30.22 J30.23 J30.24 J30.25 J30.26 J30.27 J30.28 J30.29 J30.30 J30.31 J30.32 J31.3 Q2.2(S) R9.1 R10.1 R13.1 R14.1 R21.2 R31.2 R34.2 R40.1 R42.1 R55.2 R56.2 R59.2 R60.2 SW1.3 SW1.4 U1.57(VSS) U2.2(GND) U2.3(GND) U3.2(GND) U3.17(GND) U4.1(GND1) U4.2(SE) U4.3(GND2) U5.1(GND1) U5.3(GND2) U6.4(GND) U6.5(A2) U6.6(A1) U6.7(A0) U8.2(GND) U9.2(GND) U10.5(GND) U11.5(GND) U12.2(VSS) U13.2(GND) U14.4(GND) U14.9(GND) U15.2(VSS) Y2.2 Y2.4
V3: C38.1 C76.1 U3.1(VIO) U3.6(V3)
VBAT_3V3: C68.1 J29.4 U15.5(VOUT)
VBUS_DCDC: C62.1 J29.19 L8.2 R54.1 U13.5(VIN)
VCC_3V3: C61.1 J29.10 U12.5(VOUT)
VCC_12V: C66.1 C67.1 CD1.1 D15.C R58.1 S1.3 S1.4 U14.7(IN)
VDD_DMIC: C35.1 C36.1 R61.2 U4.6(POWER) U5.2(SE) U5.6(POWER)
VDDF: C14.1 U1.27(VDDF) VDDF.1(TP)
AIN_LINEIN_N: C73.2
AIN_LINEIN_N (page 005_INTERFACE): J7.37
AIN_LINEIN_P: C26.2
AIN_LINEIN_P (page 005_INTERFACE): J7.33
AIN_MIC_N: C74.2
AIN_MIC_N (page 005_INTERFACE): J7.35
AIN_MIC_P: C21.2
AIN_MIC_P (page 005_INTERFACE): J7.31
CAN1_3V3: R64.2 U8.5(VIO)
CAN1_5V: C39.2 C40.2 R68.2 U8.3(VCC)
CAN2_3V3: R67.2 U9.5(VIO)
CAN2_5V: C44.2 C45.2 R69.2 U9.3(VCC)
CAN_5V: C49.1 Q1.3(D) R31.1 R68.1 R69.1
CAN_CANH: R29.1 U8.7(CANH)
CAN_CANH2: R36.1 U9.7(CANH)
CAN_CANL: R30.1 U8.6(CANL)
CAN_CANL2: R37.1 U9.6(CANL)
CANH: D8.2 J15.2 J16.3 J16.4 J17.2 R29.2
CANH2: D9.2 J19.2 J20.3 J20.4 J21.2 R36.2
CANL: D8.1 J16.5 J16.6 J17.1 J18.2 R30.2
CANL2: D9.1 J20.5 J20.6 J21.1 J22.2 R37.2
DCDC_12V: C57.1 C58.1 D14.C R53.1 S1.1 S1.6
DM2: D2.2(CATHODE) J8.A7(DM1) J8.B7(DM2) U3.8(VD-)
DMICCK: R9.2 R10.2 U4.4(CLOCK) U5.4(CLOCK)
DMICCK (page 005_INTERFACE): J6.13
DMICDAT: U4.5(DATA) U5.5(DATA)
DMICDAT (page 005_INTERFACE): J6.15
DP2: D1.2(CATHODE) J8.A6(DP1) J8.B6(DP2) U3.7(VD+)
EXT_3V3: J9.7(3) J29.6 J29.8
EXT_12V: D15.A J16.1 J16.2 J20.1 J20.2 J25.1 J25.2 J27.1 J27.2 J31.4
I3C_3V3: C37.1 R12.2 R63.2 U6.8(VCC)
I3C_ALERT: J6.11 R12.1 U6.3(ALERT)
I3C_SCL: J6.39 U6.2(SCL)
I3C_SDA: J6.37 U6.1(SDA)
LDO_3V3: J29.7 J29.9 R61.1 R63.1 R64.1 R65.1 R66.1 R67.1 R70.1
LDO_5V: C63.2 C64.1 C65.2 J29.24 R57.1 U14.2(OUT)
LDO_VBUS: C48.1 D17.A D18.A J29.21 J29.23 Q1.2(S) R33.1
LED_B: J7.25 R17.1
LED_G: J7.29 R19.1
LED_R: J7.23 R16.1
LED_W: J7.27 R18.1
LIN1_3V3: R39.1 R51.2 R65.2
LIN1_12V: C52.2 D10.A R71.2 U10.7(VSUP)
LIN2_3V3: R41.1 R52.2 R70.2
LIN2_12V: C56.2 D11.A R72.2 U11.7(VBAT)
LIN_12V: J29.18 R71.1 R72.1
LIN_EN1: J6.5
LIN_EN1 (page 006_CAN&LIN): R43.1
LIN_EN2: J7.15
LIN_EN2 (page 006_CAN&LIN): R44.1
LIN_LIN1: C55.2 D12.2(CATHODE) J23.2 J25.5 J25.6 J31.2 U10.6(LIN)
LIN_LIN2: C54.2 D13.2(CATHODE) J24.2 J27.5 J27.6 J31.1 U11.6(LIN)
LIN_RXD1: J6.3
LIN_RXD1 (page 006_CAN&LIN): R39.2 U10.1(RXD)
LIN_RXD2: J7.17
LIN_RXD2 (page 006_CAN&LIN): R41.2 U11.1(RXD)
LIN_TXD1: J6.7
LIN_TXD1 (page 006_CAN&LIN): R47.1
LIN_TXD2: J6.1
LIN_TXD2 (page 006_CAN&LIN): R49.1
TL_ANT: C3.1 L1.1 U1.43(ANT)
TL_AVDD1P2: AVDD1P2.1(TP) C18.1 R138.2 U1.26(AVDD1P2)
TL_CAN_RXD: J6.31
TL_CAN_RXD2: J6.27
TL_CAN_RXD2 (page 006_CAN&LIN): C46.2 U9.4(RXD)
TL_CAN_RXD (page 006_CAN&LIN): C43.2 U8.4(RXD)
TL_CAN_STB: J6.33
TL_CAN_STB2: J6.35
TL_CAN_STB2 (page 006_CAN&LIN): R24.2
TL_CAN_STB (page 006_CAN&LIN): R22.2
TL_CAN_TXD: J6.29
TL_CAN_TXD2: J6.25
TL_CAN_TXD2 (page 006_CAN&LIN): U9.1(TXD)
TL_CAN_TXD (page 006_CAN&LIN): U8.1(TXD)
TL_Key1: J7.1 SW3.1 SW3.2 SW4.1 SW4.2
TL_Key2: J7.3 SW5.1 SW5.2 SW6.1 SW6.2
TL_Key3: J7.5 SW3.3 SW3.4 SW5.3 SW5.4
TL_Key4: J7.7 SW4.3 SW4.4 SW6.3 SW6.4
TL_MICBIAS: R4.1
TL_MICBIAS (page 005_INTERFACE): J7.13
TL_PA0: U1.16(PA0)
TL_PA0 (page 005_INTERFACE): J7.10
TL_PA1: U1.17(PA1)
TL_PA1 (page 005_INTERFACE): J7.12
TL_PA2: U1.18(PA2)
TL_PA2 (page 005_INTERFACE): J7.14
TL_PA7: U1.19(PA7)
TL_PA7 (page 005_INTERFACE): R135.2
TL_PB0: U1.45(PB0)
TL_PB0 (page 005_INTERFACE): J6.2 J10.1 J10.3
TL_PB1: U1.46(PB1)
TL_PB1 (page 005_INTERFACE): J6.4
TL_PB2: U1.47(PB2)
TL_PB2 (page 005_INTERFACE): J6.6
TL_PB3: U1.48(PB3)
TL_PB3 (page 005_INTERFACE): J6.8
TL_PB4: U1.29(PB4)
TL_PB4 (page 005_INTERFACE): J7.8
TL_PB5: U1.30(PB5)
TL_PB5 (page 005_INTERFACE): J7.6
TL_PB6: U1.31(PB6)
TL_PB6 (page 005_INTERFACE): J7.4
TL_PB7: U1.32(PB7)
TL_PB7 (page 005_INTERFACE): J7.2
TL_PC0: U1.35(PC0)
TL_PC0 (page 005_INTERFACE): J7.32 J7.34
TL_PC1: U1.36(PC1)
TL_PC1 (page 005_INTERFACE): J7.36 J7.38
TL_PC2: R2.2 U1.37(PC2)
TL_PC2 (page 005_INTERFACE): J7.40
TL_PC3: C6.2 U1.38(PC3) Y1.1
TL_PC3 (page 005_INTERFACE): J7.42
TL_PC4: U1.39(PC4)
TL_PC4 (page 005_INTERFACE): J7.24
TL_PC5: U1.21(PC5)
TL_PC5 (page 005_INTERFACE): J7.26
TL_PC6: U1.22(PC6)
TL_PC6 (page 005_INTERFACE): J7.28
TL_PC7: U1.23(PC7)
TL_PC7 (page 005_INTERFACE): J7.30
TL_PD0: U1.49(PD0)
TL_PD0 (page 005_INTERFACE): J6.9
TL_PD4: U1.12(PD4)
TL_PD4 (page 005_INTERFACE): J7.16 J9.8(4)
TL_PD5: U1.11(PD5)
TL_PD5 (page 005_INTERFACE): J7.18 J9.6
TL_PD6: U1.10(PD6)
TL_PD6 (page 005_INTERFACE): J7.20 J9.2(10)
TL_PD7: U1.9(PD7)
TL_PD7 (page 005_INTERFACE): J7.22 J9.4(8)
TL_PE0: U1.14(PE0)
TL_PE0 (page 005_INTERFACE): J6.38
TL_PE2: U1.15(PE2)
TL_PE2 (page 005_INTERFACE): J6.40
TL_PF4: U1.50(PF4)
TL_PF4 (page 005_INTERFACE): J6.12
TL_PF5: U1.51(PF5)
TL_PF5 (page 005_INTERFACE): J6.14
TL_PF6: U1.52(PF6)
TL_PF6 (page 005_INTERFACE): J6.16
TL_PF7: U1.53(PF7)
TL_PF7 (page 005_INTERFACE): J6.18
TL_PG0: U1.54(PG0)
TL_PG0 (page 005_INTERFACE): J6.20
TL_PG1: U1.55(PG1)
TL_PG1 (page 005_INTERFACE): J6.22
TL_PG2: U1.56(PG2)
TL_PG2 (page 005_INTERFACE): J6.17
TL_PG7: U1.1(PG7)
TL_PG7 (page 005_INTERFACE): J6.23
TL_PH0: U1.2(PH0)
TL_PH0 (page 005_INTERFACE): J6.24
TL_PH2: U1.3(PH2)
TL_PH2 (page 005_INTERFACE): J6.26
TL_PH3: U1.4(PH3)
TL_PH3 (page 005_INTERFACE): J6.28
TL_PH4: U1.5(PH4)
TL_PH4 (page 005_INTERFACE): J6.30
TL_PH5: U1.6(PH5)
TL_PH5 (page 005_INTERFACE): J6.32
TL_PH6: U1.7(PH6)
TL_PH6 (page 005_INTERFACE): J6.34
TL_PH7: U1.8(PH7)
TL_PH7 (page 005_INTERFACE): J6.36
TL_RF: C5.1 D16.2(CATHODE) J1.1 L2.2
TL_RST: C8.1 SW1.1 SW1.2 U1.42(POR)
TL_SDMN0: L6.1
TL_SDMN0 (page 005_INTERFACE): J7.19
TL_SDMN1: L4.1
TL_SDMN1 (page 005_INTERFACE): J7.39
TL_SDMP0: L7.1
TL_SDMP0 (page 005_INTERFACE): J7.21
TL_SDMP1: L5.1
TL_SDMP1 (page 005_INTERFACE): J7.41
TL_VBAT: C15.1 J29.1 J29.3 J29.5 U1.28(VBAT)
TL_VDD1P2: C72.1 L3.2 R138.1 R139.1 VDD1P2.1(TP)
TL_VDD3DCDC: C17.1 R141.2 U1.24(VDD3DCDC) VDD3DCDC.1(TP)
TL_VDDCORE: C16.1 U1.20(VDDCORE) VDDCORE.1(TP)
TL_VDDIOPE: C13.1 R140.2 U1.13(VDDIOPE) VDDIOPE.1(TP)
TL_VDDO3: C12.1 J9.1(9) R20.2 R140.1 R141.1 U1.33(VDDO3) VDDO3.1(TP)
TL_VLINE: C1.1 C2.1 R139.2 U1.44(VLINE) VLINE.1(TP)
TL_XC1: C11.1 U1.40(XC1) Y2.3
TL_XC2: C9.2 U1.41(XC2) Y2.1
UART_5V: C75.1 C77.1 R62.1 U3.3(VDD5) U3.9(VBUS)
UART_RX: J6.21 R136.2
UART_TX: J6.19 R137.2
USB_5V: J29.20 J29.22 R15.1 R62.2
USB_VBUSU: C71.1 D3.2(CATHODE) J8.A4B9(VBUS) J8.B4A9(VBUS) R15.2
N20253886: C22.1 R4.2 U2.4(VDD)
N20253935: C21.1 U2.1(OUTPUT)
N20253959: C26.1 J3.3
N20337202: C19.2 C23.1 L4.2 R3.1
N20337204: C20.2 J2.2 R3.2
N20337251: C23.2 C24.1 L5.2 R5.1
N20337259: C25.1 J2.3 R5.2
N20337346: C27.2 C31.1 L6.2 R7.1
N20337363: C28.2 J4.2 R7.2
N20337410: C31.2 C32.1 L7.2 R8.1
N20337418: C33.1 J4.3 R8.2
N20392329: D4.A(ANODE) R16.2
N20392898: D5.A(ANODE) R17.2
N20393445: D6.A(ANODE) R18.2
N20393873: D7.A(ANODE) R19.2
N20432643: C4.1 L1.2 L2.1
N20432803: C7.2 R2.1 Y1.2
N20433121: C10.1 U1.34(VMID)
N20433225: L3.1 U1.25(DCDCSW)
N20446669: D14.A L8.1 U13.1(SW)
N20446778: C59.2 C60.1 D17.C U12.1(VIN) U12.3(CE)
N20446804: C57.2 R53.2 R55.1 U13.3(FB)
N20446808: R54.2 R56.1 U13.4(EN)
N20447279: C65.1 R57.2 R59.1 U14.3(ADJ)
N20447283: R58.2 R60.1 U14.6(EN)
N20449113: J8.A5(CC1) R13.2
N20449208: J8.B5(CC2) R14.2
N20451817: J15.1 R28.1
N20451819: C47.1 R28.2 R32.2
N20451956: J18.1 R32.1
N20451988: J19.1 R35.1
N20451990: C50.1 R35.2 R38.2
N20452190: J22.1 R38.1
N20458083: R22.1 U8.8(STB)
N20458950: Q1.1(G) Q2.3(D) R33.2
N20458968: Q2.1(G) R34.1 R66.2
N20459724: R40.2 U10.8(INH)
N20459777: R45.2 U10.3(WAKE)
N20459821: R46.2 U11.3(WAKE_N)
N20459876: C51.2 R47.2 U10.4(TXD)
N20459892: D10.C R48.2
N20459907: C53.2 R49.2 U11.4(TXD)
N20481050: C69.2 C70.1 D18.C U15.1(VIN) U15.3(CE)
N20505812: C73.1 J3.2
N20509362: TP4.1(TP) U3.12(DTR)
N20509364: TP5.1(TP) U3.11(DCD)
N20509368: TP6.1(TP) U3.10(ACT#)
N20509433: TP8.1(TP) U3.13(RTS)
N20509448: TP7.1(TP) U3.14(DSR)
N20509463: TP9.1(TP) U3.15(CTS)
N20509471: TP10.1(TP) U3.16(RI)
N20509473: R136.1 U3.5(RXD)
N20509515: R137.1 U3.4(TXD)
N20515406: R45.1 R51.1
N20515407: R24.1 U9.8(STB)
N20515412: R44.2 U11.2(SLP_N)
N20515414: J24.1 R50.1
N20515421: R43.2 U10.2(EN)
N20515425: J23.1 R48.1
N20515428: R42.2 U11.8(INH)
N20515429: D11.C R50.2
N20515430: R46.1 R52.1
N20515731: J10.4 R20.1
N20515733: J10.2 R21.1
N20515774: J9.9(1) R135.1

Not connected (* = marked no-connect by the designer): J2 4*; J3 4*; J4 4*; J6 10*; J7 9* 11*; J8 A8(SBU1)* B8(SBU2)*; J9 10(2)*; J29 2; U12 4(NC)*; U13 6(NC)*; U14 1(NC1)* 5(NC3)* 8(NC2)*; U15 4(NC)*

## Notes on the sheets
sheet 2
- Author
- Approved by
- Shouchun
- Xiang
- Date
- Note
- REV1.0
- 2025/05/13
- Initial Version
- REV1.1
- 2025/07/13
- 1.Add VDDF Net
  2.Add 12V-5V silk screen
  3.Add AVDD1P2 Net
  4.Line in
  5.DCDC cap ->10uF
  6.Modify Key footprint
- REV1.2
- 2026/03/05
- 1.Modify PCB Layout
  2.Add CE/FCC skilscreen
sheet 3
- LDO
  CE1132
  5V->3.3V
- USB POWER
  5V
- 3.3V
- DCDC
  CE8441ADJ
  5V->12V
- LDO
  SA21345
  12V->5V
- POWER
  12V
- 12V
- 3.3V
- VBAT
- CAN_1
- VSUP
- VIO
- CANH
- TXD
- TL_PH4
- CAN_1
  INTERFACE
- TJA1462
- RXD
- TL_PH5
- TL_PD4
- TL_PD5
- CANL
- KEYx4
- STB
- TL_PH6
- TL_PD6
- TL_PD7
- CAN_2
- VSUP
- VIO
- CANH
- TXD
- TL_PH2
- TL_PC4
- TL_PC5
- CAN_2
  INTERFACE
- LEDx4
- CANL
- TJA1462
- RXD
- TL_PH3
- TL_PC6
- STB
- TL_PH7
- TL_PC7
- RESET
  KEY
- RESETB
- LIN
- TL3225B
  QFN56B
- LIN
- LIN_TXD
- TL_PB3
- 24MHZ
  CRYSTAL
- XC1/XC2
- LIN1
  INTERFACE
- GND
- SIT1021
- LIN_RXD
- TL_PB1
- 12V
- TL_PA7
- SWS
- LIN_SLP_N
- TL_PB2
- ANT
  IFA&SMA
- RF
- LIN
- TL_PC2
- 32K
  CRYSTAL
- LIN
- LIN_TXD
- TL_PB0
- TL_PC3
- LIN2
  INTERFACE
- GND
- SIT1021
- LIN_RXD
- TL_PD5
- 12V
- LIN_SLP_N
- TL_PD4
- USB
- TL_PG0
- TL_PG1
- CH340
- TL_PE0
- TL_PD6
- TL_PE2
- I3C
- TL_PD7
- P3T1750DP
- SDMx2
- TL_PF4
- TL_PC0
- TL_PC1
- TL_PF5
- DMIC
- TL_PF6
- LINEINx1
  AMICx1
- TL_PC2
- TL_PC3
- GPIOx42
sheet 4
- ==VDDIOPE==
- ==PA==
- ==PH==
- SWS
- ==PF==
- RF
- ==PG==
- ==PD==
- JTAG_TDI
- JTAG_TDO
- JTAG_TMS
- JTAG_TCK
- ==PC==
- AMIC
- Crystal
- AMIC
- 32K
- 32K
- ==PB==
- PB0
  + low, 4-wire jtag
  + high, 2-wire jtag
sheet 5
- LINE IN & AMIC1
- SDM1
- SDMN1
- SDMP1
- SDM0
- DMIC
- SDMN0
- SDMP0
sheet 6
- ==VDDIOPE==
- ==PH==
- I3C1_SDA
- I3C1_SCL
- ==PA==
- SWS
- ==PF==
- ==PD==
- JTAG_TDI
- I3C
- VCC 1.4V-3.6V
- JTAG_TDO
- ==PG==
- JTAG_TMS
- JTAG_TCK
- ==PC==
- AMIC
- AMIC
- 32K
- 32K
- ==PB==
- PB0
  + low, 4-wire jtag
  + high, 2-wire jtag
- USB Type-C
- SWS
- JTAG_TCK
- JTAG_TMS
- JTAG_TDO
- JTAG_TDI
- LED
- KEY
- JTAG option
- PIN3 to 4: JTAG, 2 wire
- PIN1 to 2: JTAG, 4 wire
sheet 7
- CAN
- VCC 5V
- VCC 5V
- 12V
- CANH
- CANL
- GND
- SPLIT_TERM
- 12V
- CANH
- CANL
- SPLIT_TERM
- GND
- Common mode inductors are reserved
  for the following models,
  and 0R resistors are placed by default.
  muRata：DLW31SH222SQ2L
  TDK：ACT1210-110-2P-TL00
- LIN1
- LIN2
- VSUP 4.5V-36V
- VBAT5.5V-27V
- 主节点总线需接电阻与二极管，而从节点总线到地接 220pF 电容
sheet 8
- 5V->12V
- 12V->5V
- TOP
- BOTTOM
- LDO:5V-3V3
- 5V-12V Booster
- DCDC_12V=0.6V*(1+R30/R32)
- LDO:12V-5V
- V_OUT=0.6V*(1+R34/R36)
- The voltage output
  configuration options
- VCC_LDO
- 5V
- R18
- 240K
- R19
- 32.4K
